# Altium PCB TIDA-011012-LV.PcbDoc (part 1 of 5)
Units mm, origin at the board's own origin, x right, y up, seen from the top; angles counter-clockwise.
Board outline 250 x 280 mm, 4 copper layers (Top Layer, Layer 1, Layer 2, Bottom Layer), stack 2.208 mm thick; 410 components, 230 nets, 1280 pads, 1868 vias.
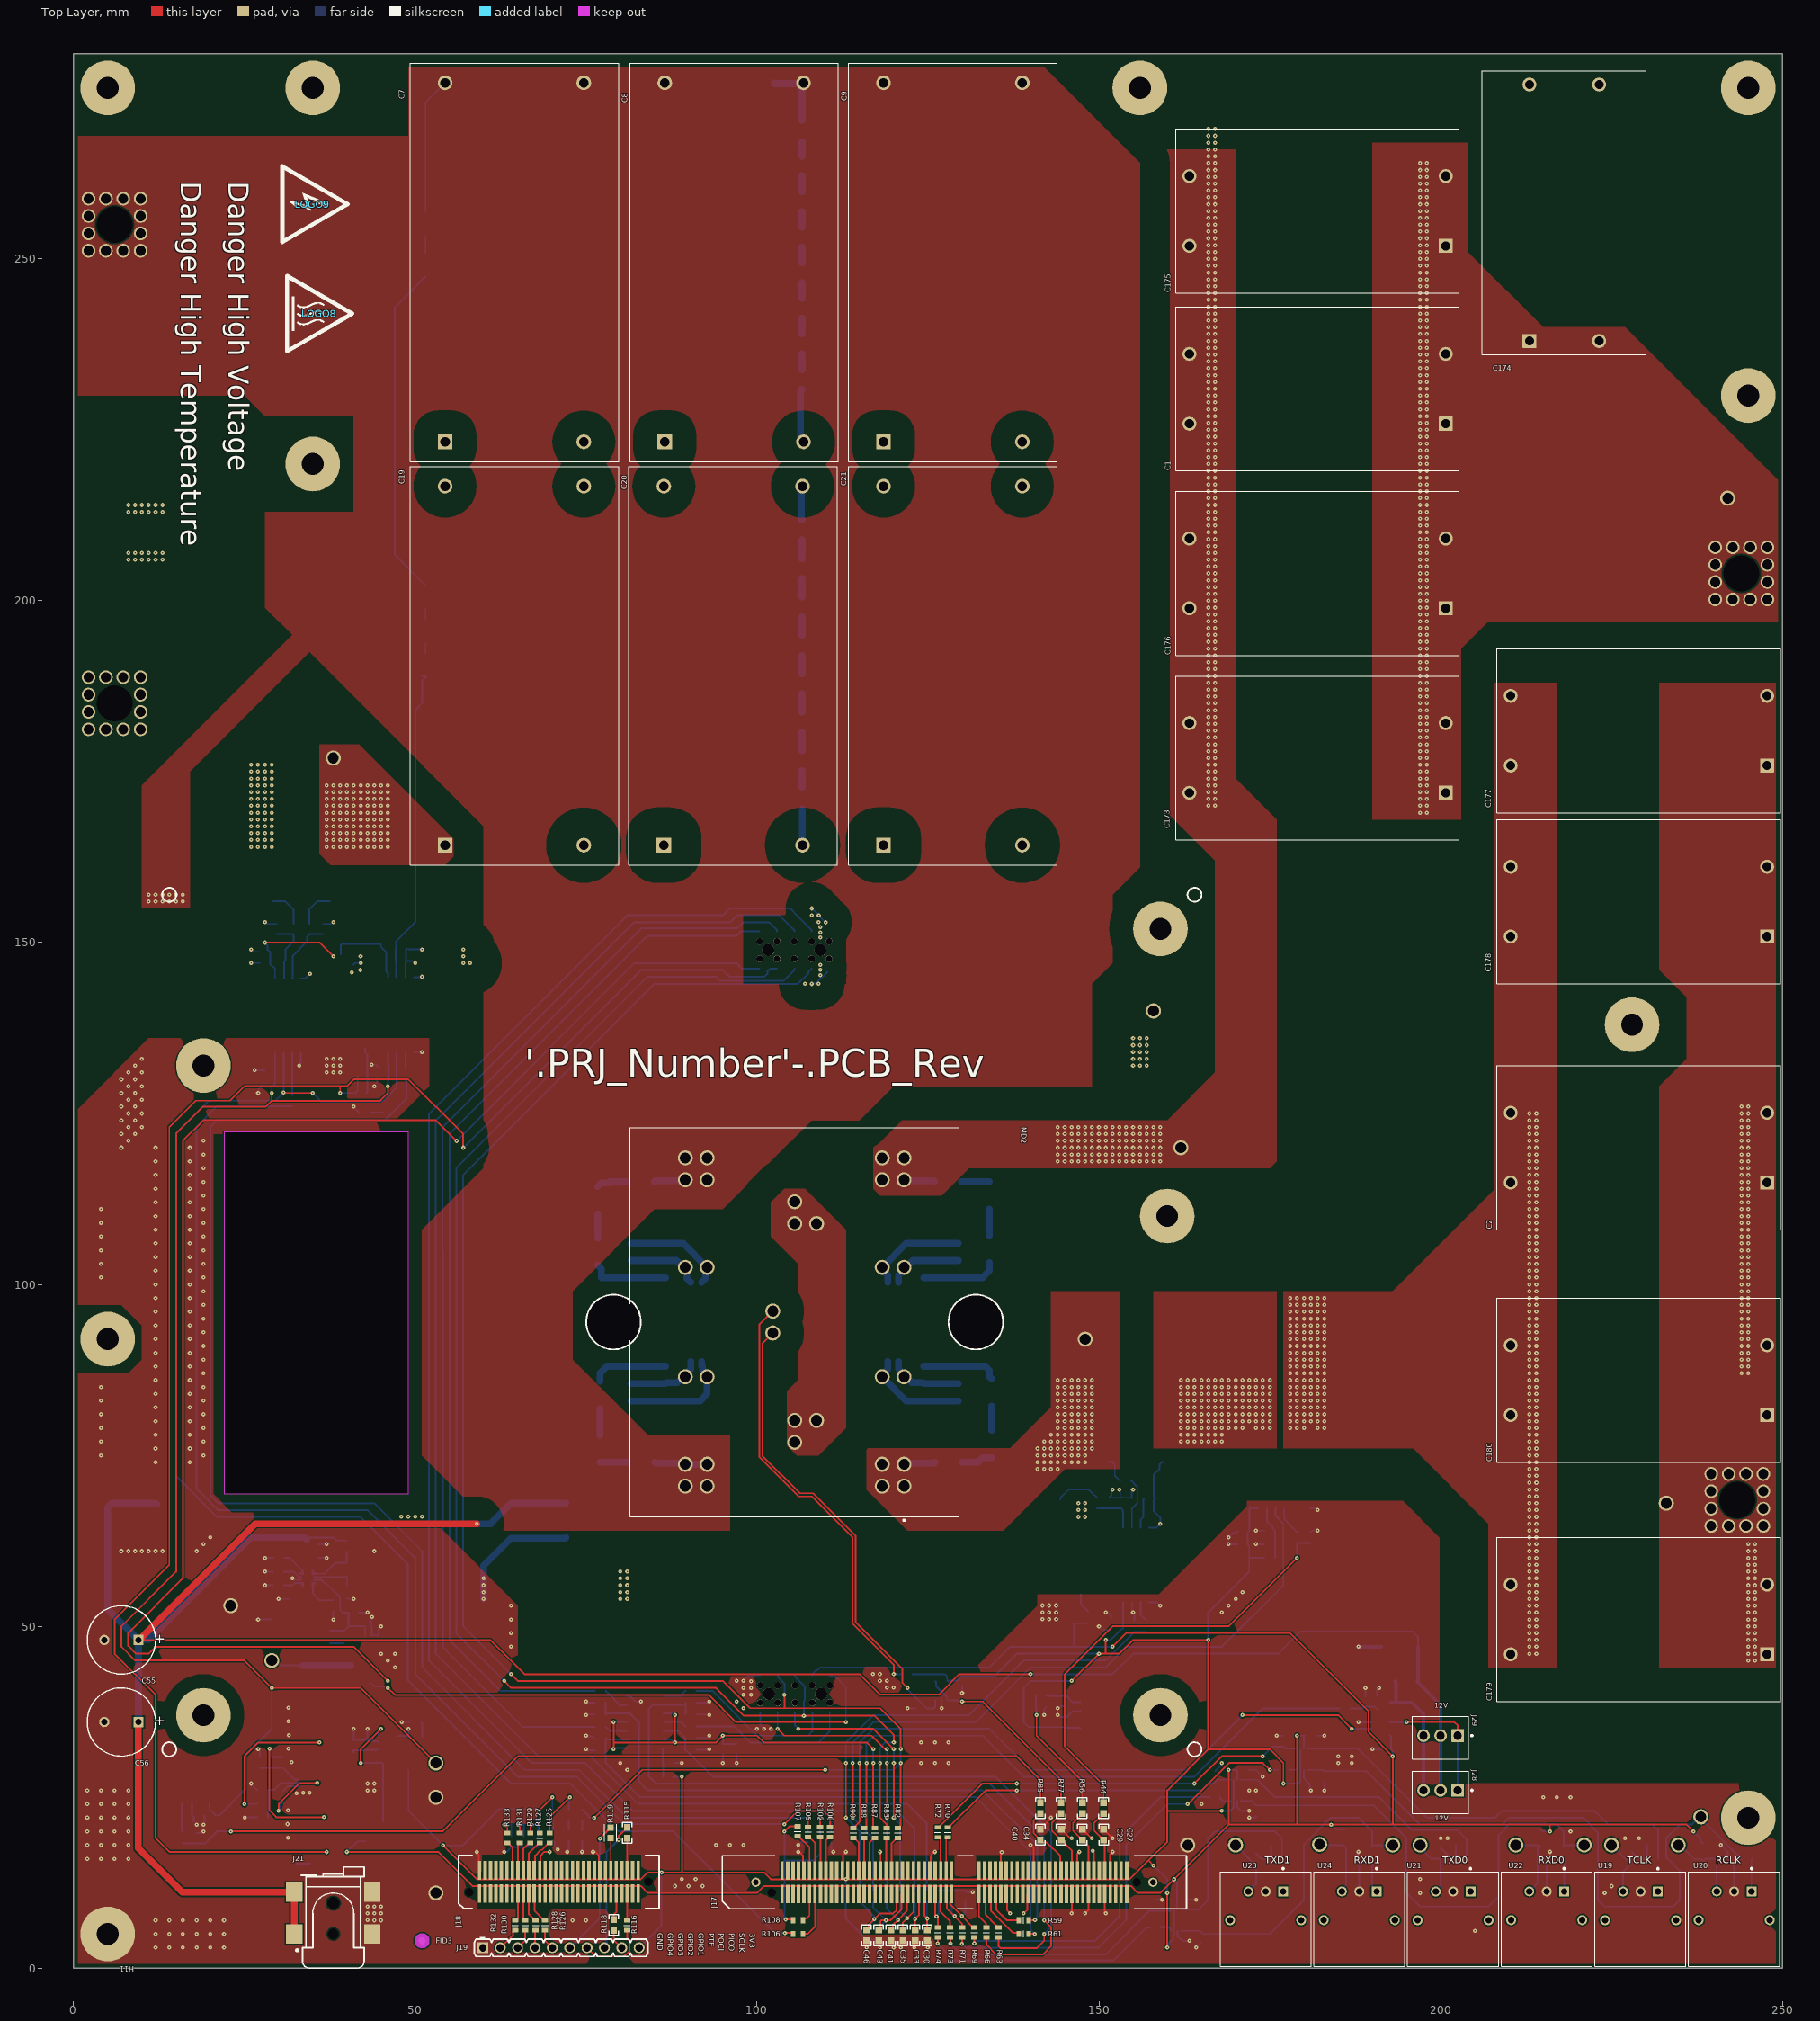
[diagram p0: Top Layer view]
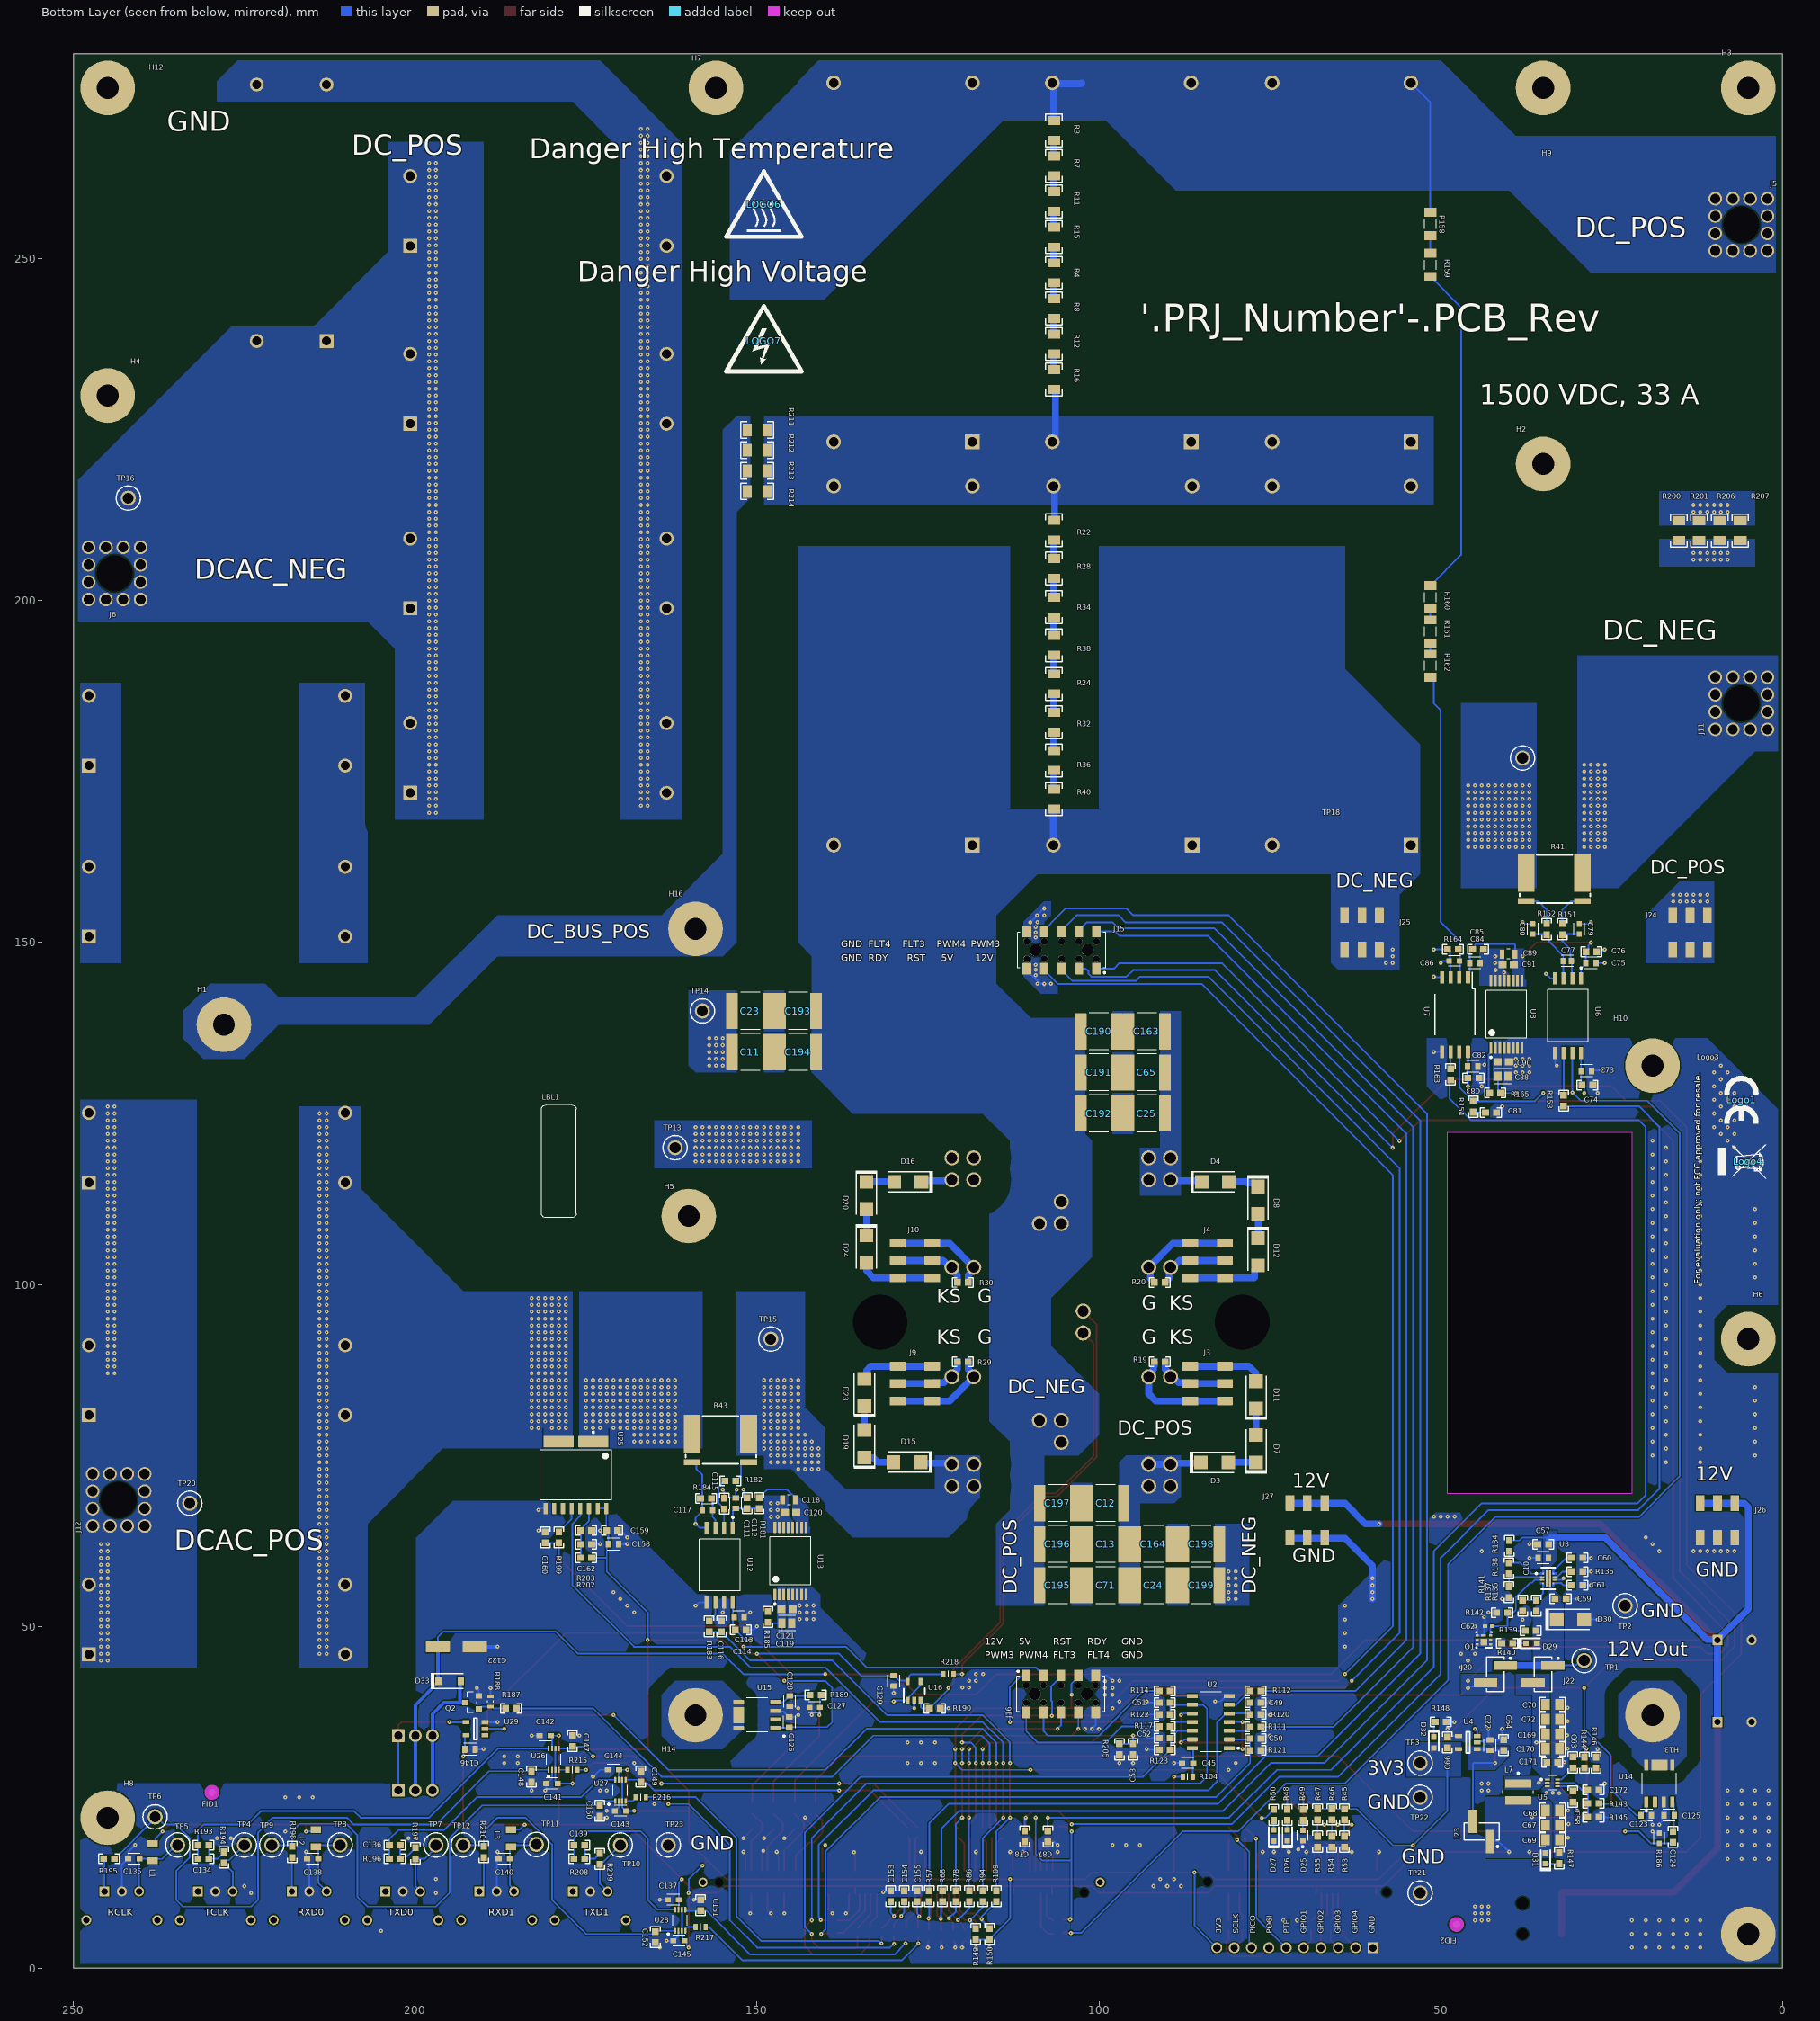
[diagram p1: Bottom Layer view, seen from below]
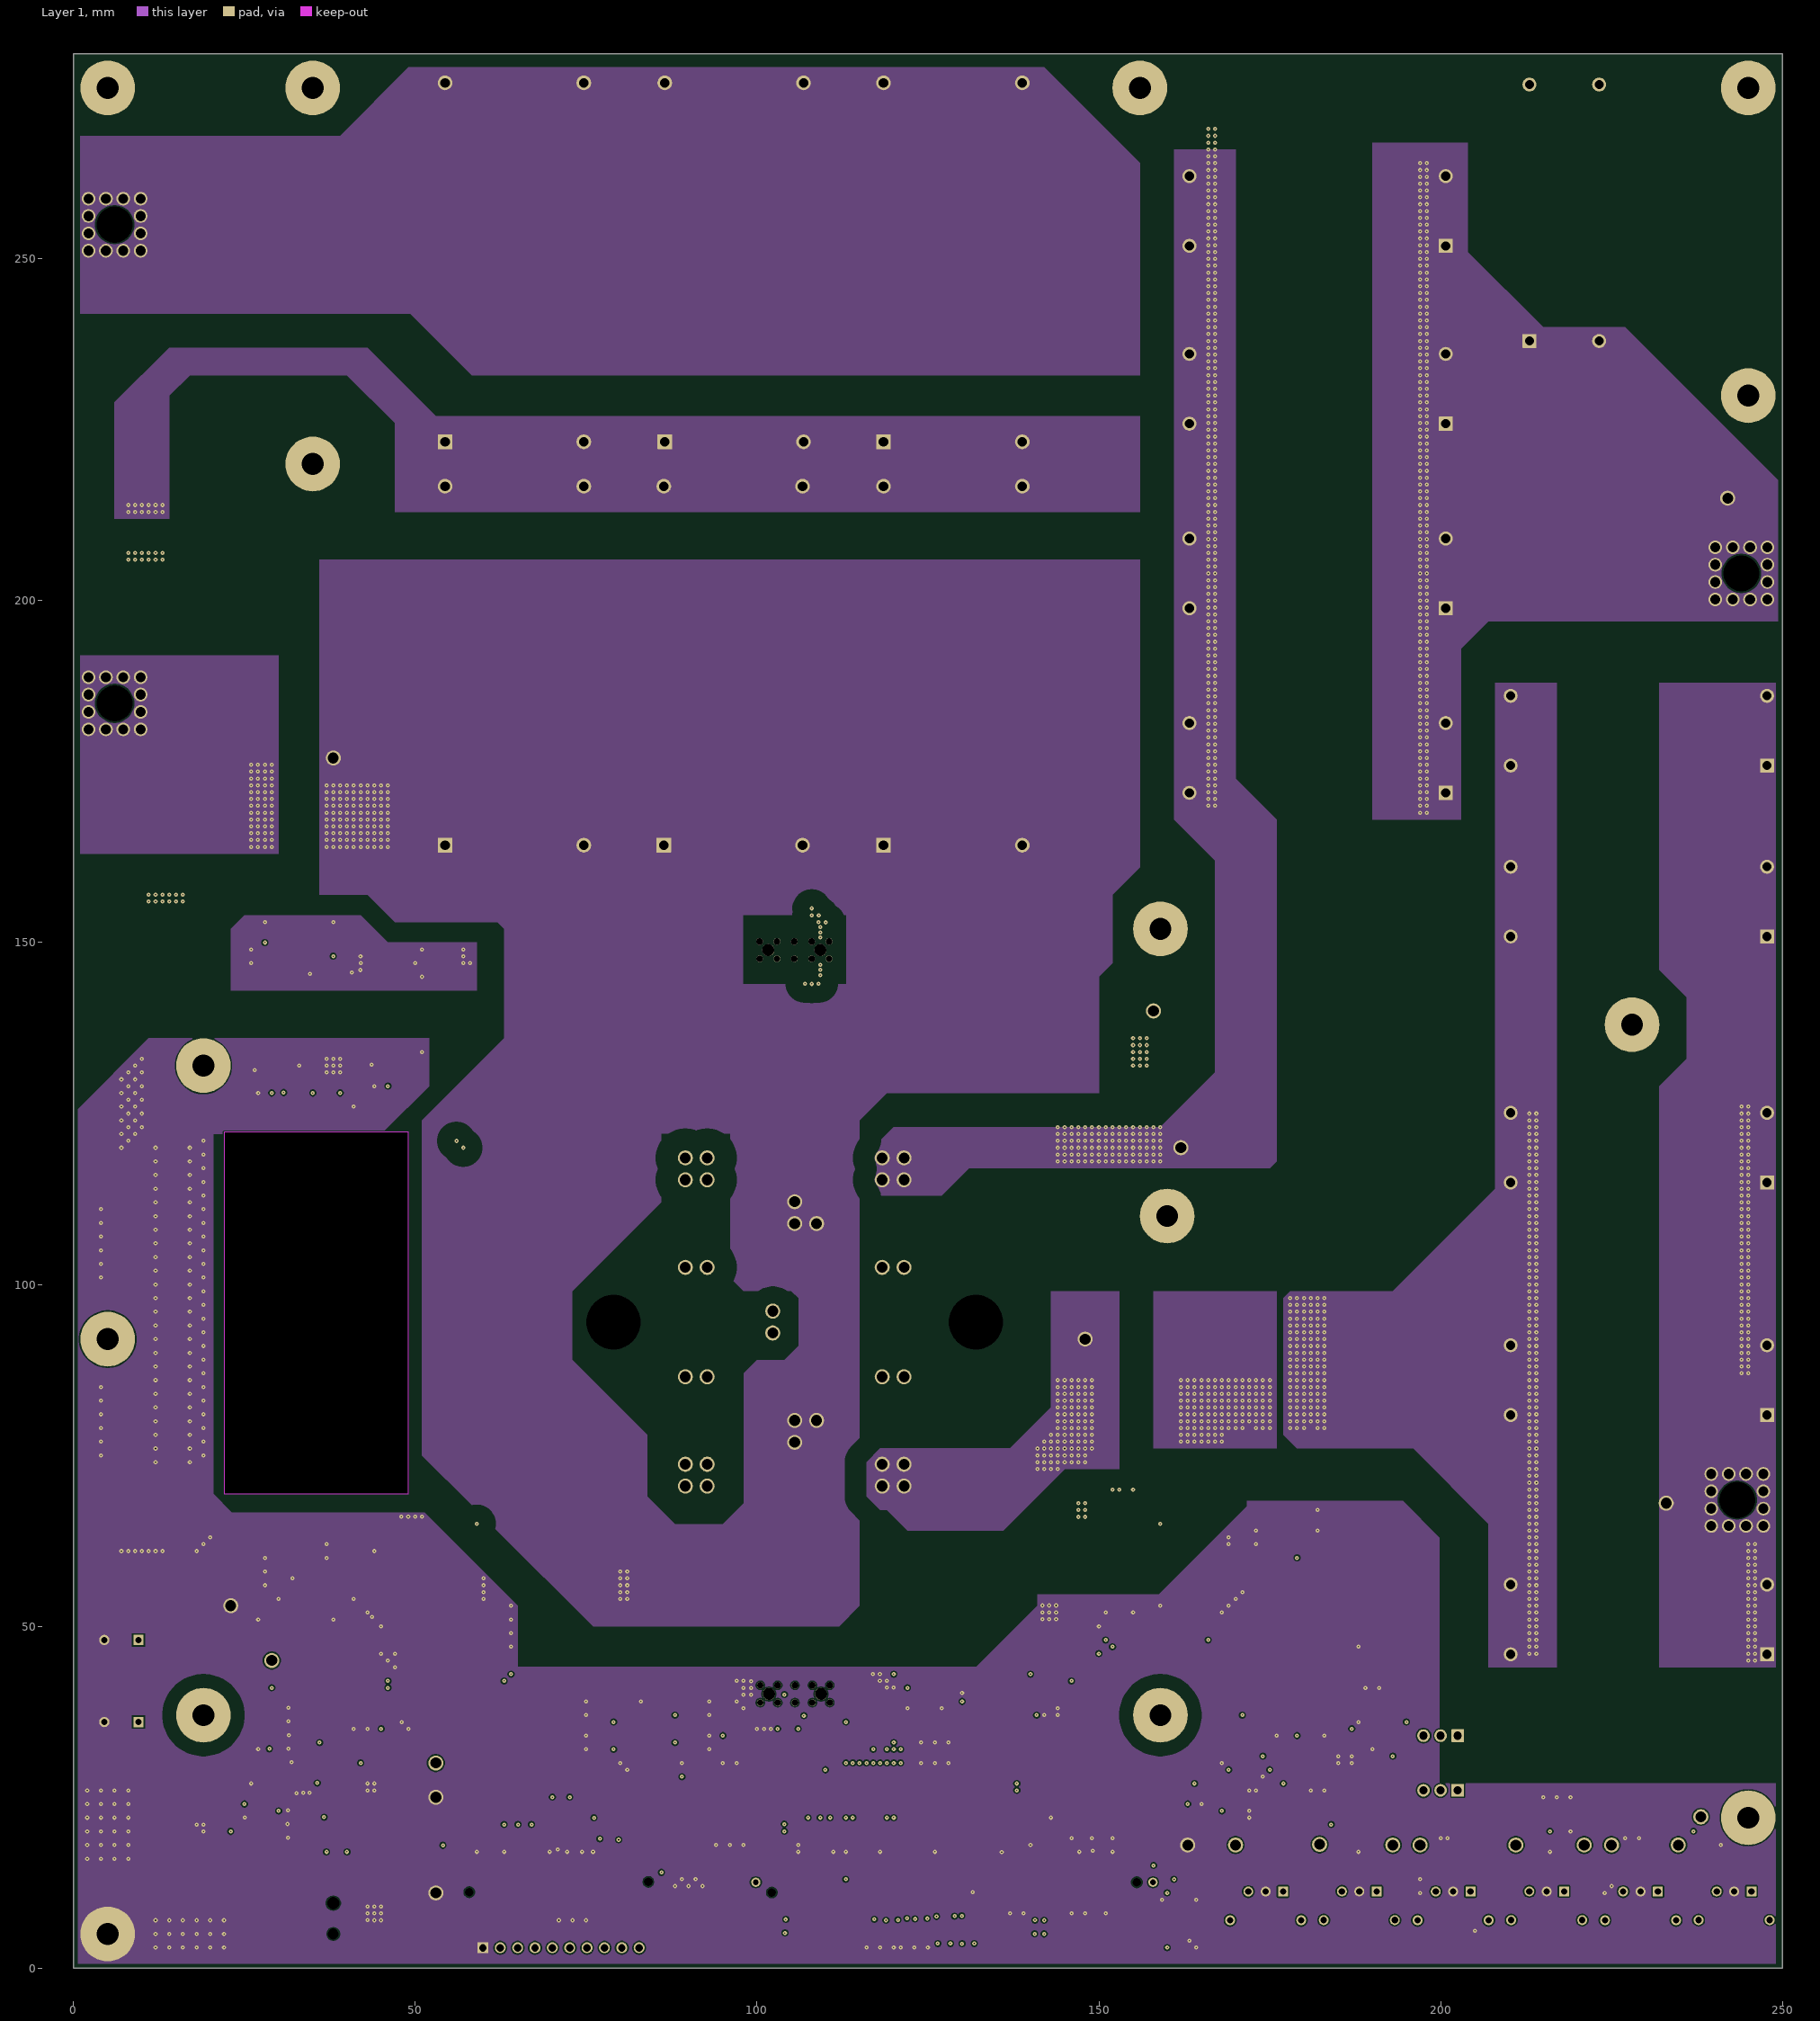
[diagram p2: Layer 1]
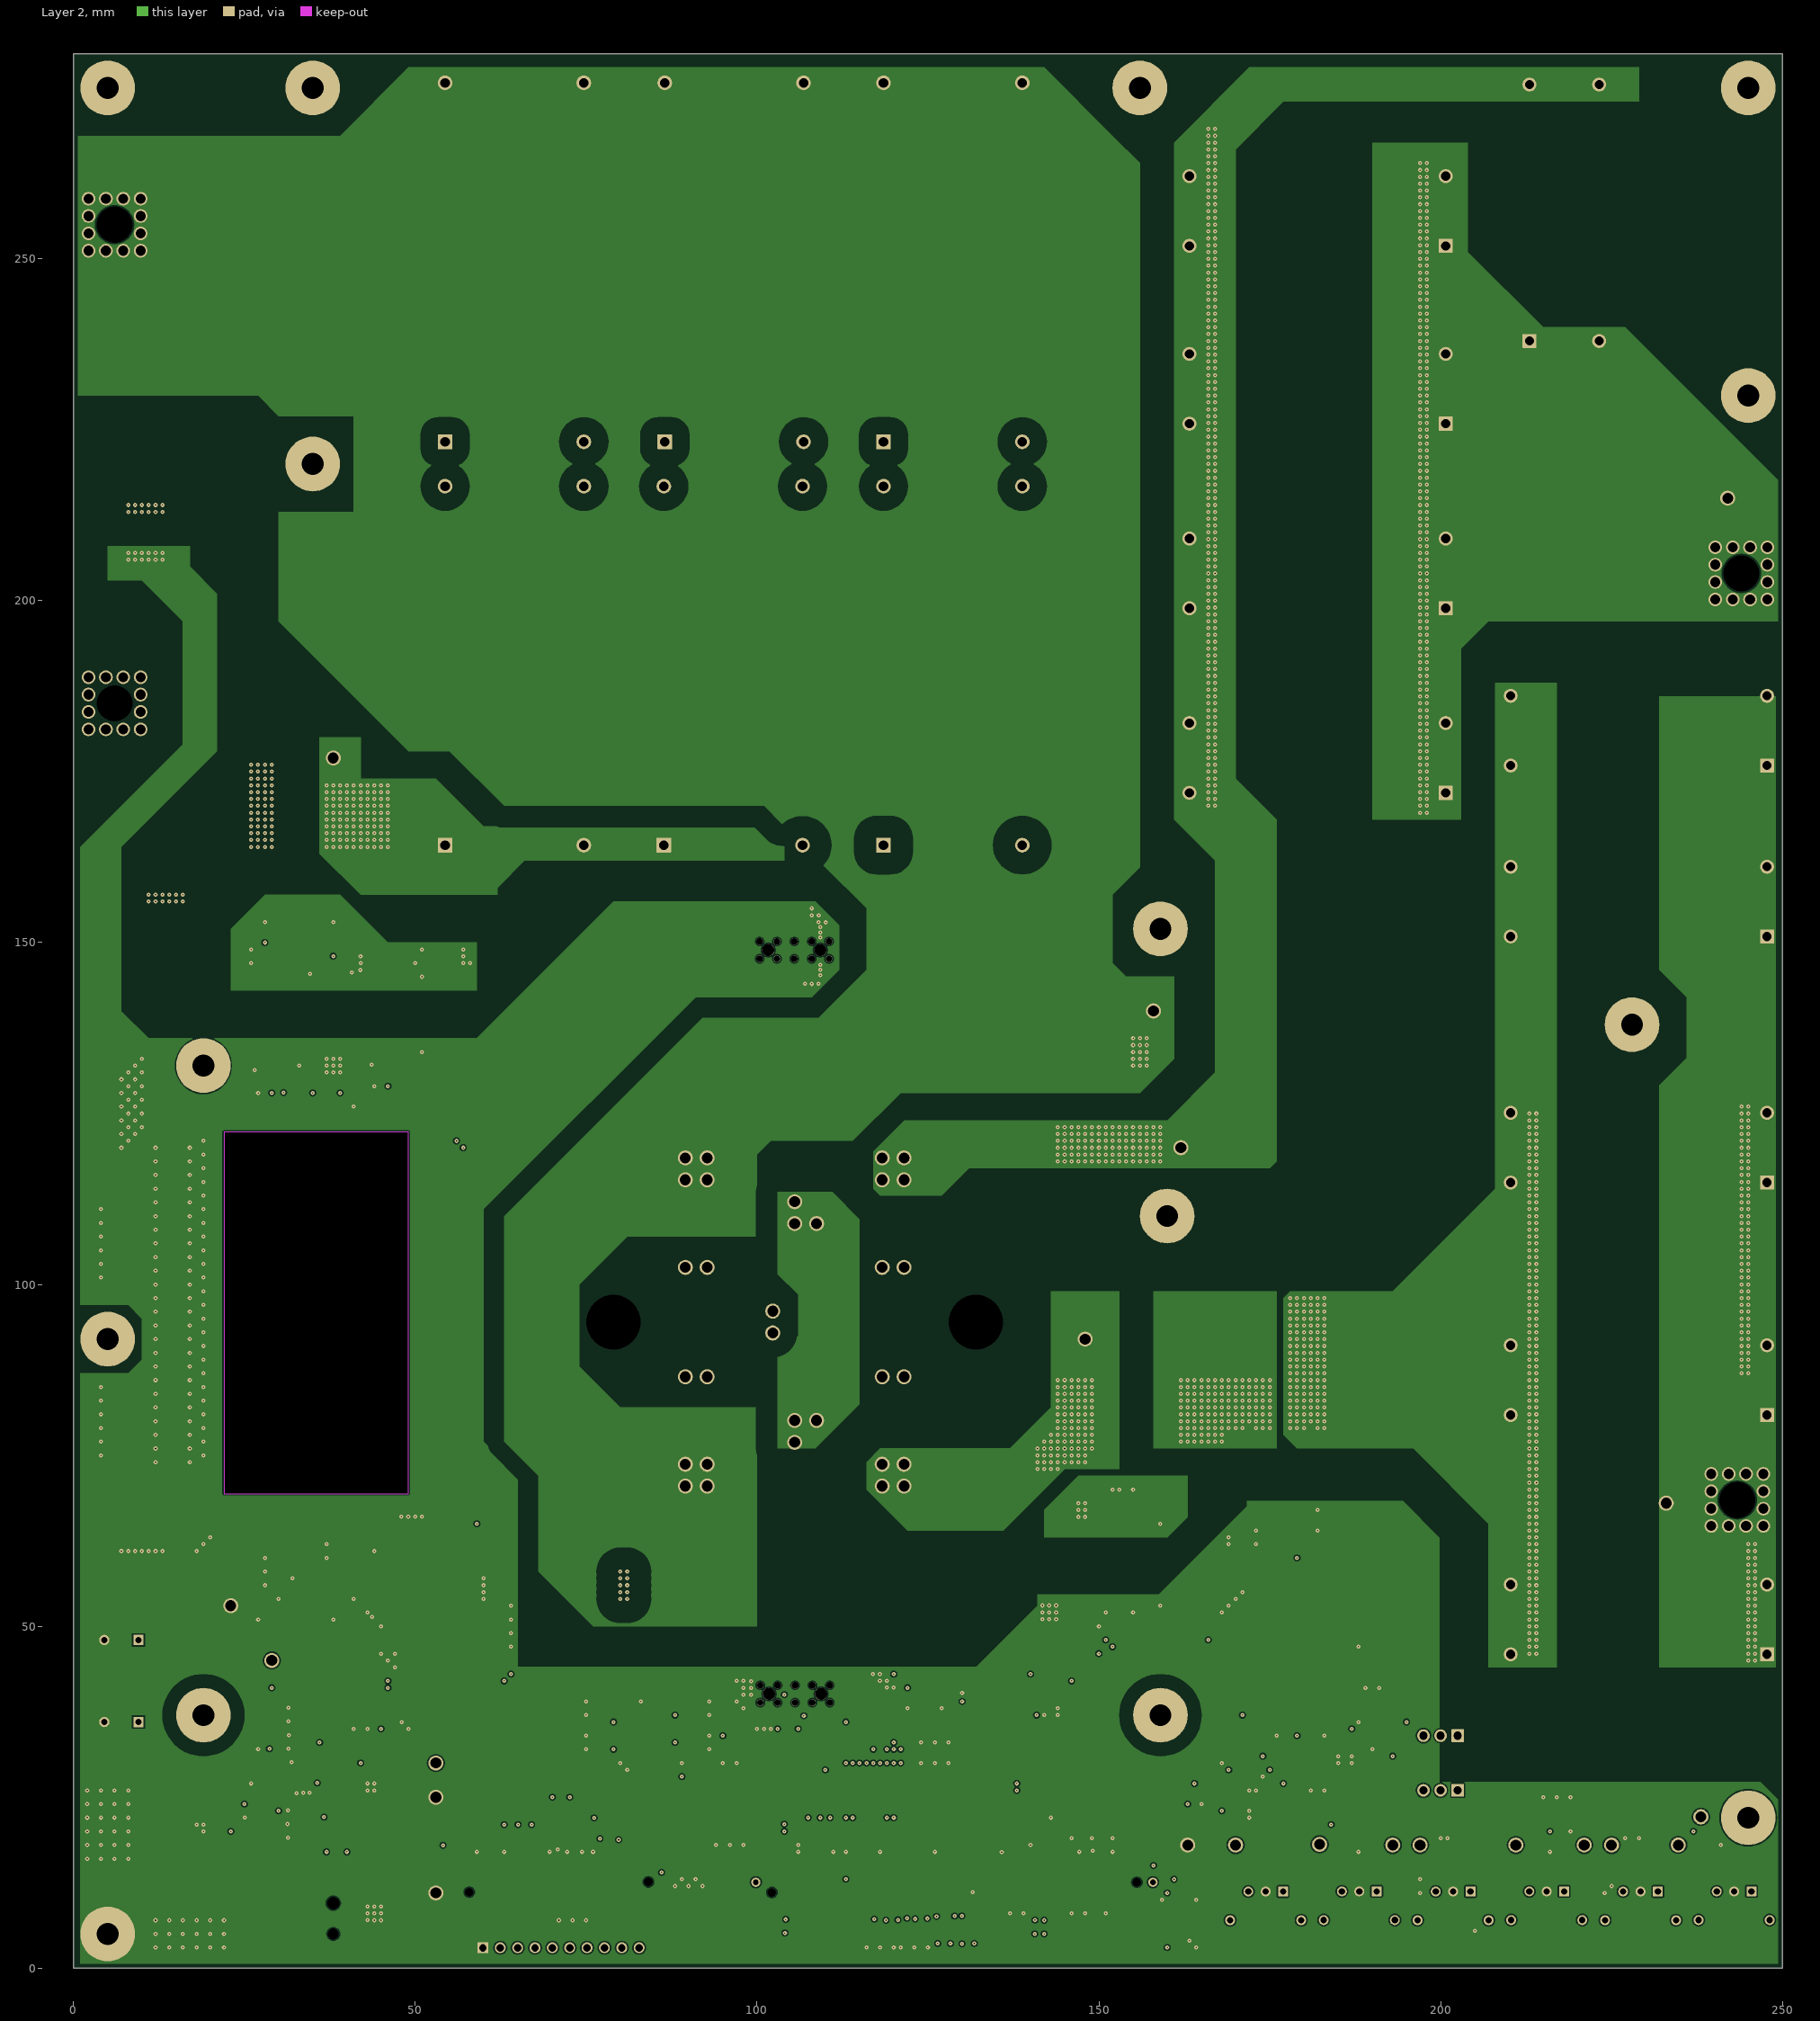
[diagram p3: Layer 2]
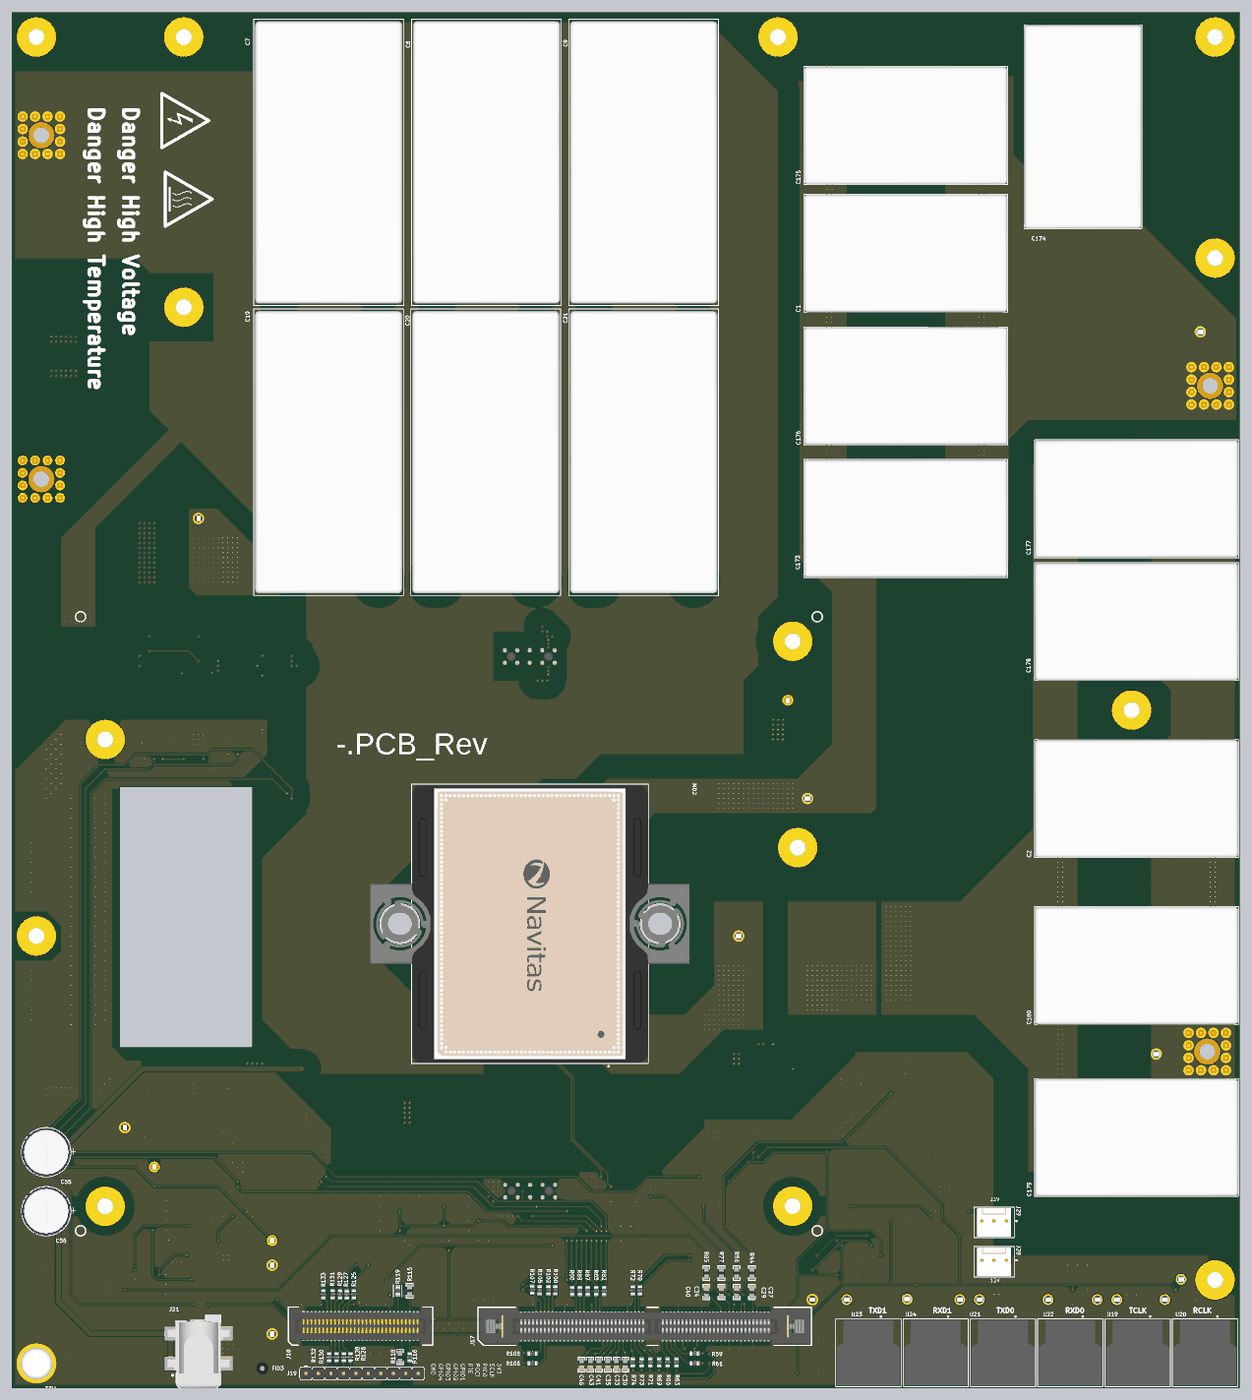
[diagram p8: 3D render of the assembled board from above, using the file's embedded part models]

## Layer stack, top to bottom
Top Solder: solder mask 0.0102, Solder Resist, Dk 3.5
Top Layer: signal copper 0.105
Dielectric 3: prepreg 0.0711, PP-006, Dk 4.1
Dielectric 1: prepreg 0.0711, PP-006, Dk 4.1
Layer 1: signal copper 0.105
Dielectric1: core 1.5037, FR-4 High Tg, Dk 4.8
Layer 2: signal copper 0.105
Dielectric 2: prepreg 0.0711, PP-006, Dk 4.1
Dielectric 4: prepreg 0.0711, PP-006, Dk 4.1
Bottom Layer: signal copper 0.105
Bottom Solder: solder mask 0.0102, Solder Resist, Dk 3.5

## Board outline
0,0 250,0 250,280 0,280
cut-out: 22,69.4 49,69.4 49,122.3 22,122.3

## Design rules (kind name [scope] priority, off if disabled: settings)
AcuteAngle [All] p1: minimum=4.50000000000000E+0001 checktracksonly=FALSE
AssemblyTestPointUsage [All] p1: valid=2
BoardOutlineClearance BoardOutlineClearance_MountingHoles [OnCopper and InComponentClass('Mounting Holes')] p1: gap=1 ignorepadtopadclearanceinfootprint=FALSE
BoardOutlineClearance BoardOutlineClearance_Poly [OnCopper and IsPoly] p2: gap=0.635 ignorepadtopadclearanceinfootprint=FALSE
BoardOutlineClearance [OnCopper and Not InComponentClass('Logo') and not InComponentClass('FiducialMark') and not InRegion(1000,500,4000,800) and not InPoly] p3: gap=1.016 ignorepadtopadclearanceinfootprint=FALSE
Clearance MetalStandofftempSense [InNet('NetH13_1')OR InNet('NetH14_1')] p1: gap=2 ignorepadtopadclearanceinfootprint=TRUE
Clearance Clearance_HV_DC_P_OutLayer_A [InNetClass('HV_DC_P') and (OnLayer('Top Layer') or OnLayer('Bottom Layer') or OnLayer('Multi-Layer')) vs (InNetClass('HV_DC_N') OR InNetClass('HV_AC_N') OR InNetClass('HV_AC_P') OR InNetClass('HV_DC_SN_N') OR InNetClass('HV_DC_SN_P') )  and (OnLayer('Top Layer') or OnLayer('Bottom Layer') or OnLayer('Multi-Layer'))] p2: gap=4.4 ignorepadtopadclearanceinfootprint=TRUE
Clearance Clearance_HVM_OutLayer_A [InNetClass('HVM') and (OnLayer('Top Layer') or OnLayer('Bottom Layer') or OnLayer('Multi-Layer')) vs (InNetClass('HV_DC_N') OR InNetClass('HV_AC_N') OR InNetClass('HV_AC_P') OR InNetClass('HV_DC_SN_N') OR InNetClass('HV_DC_SN_P') OR InNetClass('HV_DC_P') )  and (OnLayer('Top Layer') or OnLayer('Bottom Layer') or OnLayer('Multi-Layer'))] p3: gap=3.5 ignorepadtopadclearanceinfootprint=TRUE
Clearance Clearance_HV_DC_N_OutLayer_A [InNetClass('HV_DC_N') and (OnLayer('Top Layer') or OnLayer('Bottom Layer') or OnLayer('Multi-Layer')) vs (InNetClass('HV_DC_P') OR InNetClass('HV_AC_N') OR InNetClass('HV_AC_P') OR InNetClass('HV_DC_SN_N') OR InNetClass('HV_DC_SN_P'))   and (OnLayer('Top Layer') or OnLayer('Bottom Layer') or OnLayer('Multi-Layer'))] p4: gap=4.4 ignorepadtopadclearanceinfootprint=TRUE
Clearance Clearance_HV_AC_N_OutLayer_A [InNetClass('HV_AC_N') and  (OnLayer('Top Layer') or OnLayer('Bottom Layer') or OnLayer('Multi-Layer')) vs (InNetClass('HV_DC_N') OR InNetClass('HV_DC_P') OR InNetClass('HV_AC_P') OR InNetClass('HV_DC_SN_N') OR InNetClass('HV_DC_SN_P')  )   and (OnLayer('Top Layer') or OnLayer('Bottom Layer') or OnLayer('Multi-Layer'))] p5: gap=4.4 ignorepadtopadclearanceinfootprint=TRUE
Clearance Clearance_HV_DC_SN_N_OutLayer_A [InNetClass('HV_DC_SN_N')  and (OnLayer('Top Layer') or OnLayer('Bottom Layer') or OnLayer('Multi-Layer')) vs (InNetClass('HV_DC_N') OR InNetClass('HV_DC_P') OR InNetClass('HV_AC_P') OR InNetClass('HV_AC_N') OR InNetClass('HV_DC_SN_P'))  and (OnLayer('Top Layer') or OnLayer('Bottom Layer') or OnLayer('Multi-Layer'))] p6: gap=4.4 ignorepadtopadclearanceinfootprint=TRUE
Clearance Clearance_HV_DC_SN_P_OutLayer_A [InNetClass('HV_DC_SN_P')  and (OnLayer('Top Layer') or OnLayer('Bottom Layer') or OnLayer('Multi-Layer')) vs (InNetClass('HV_DC_N') OR InNetClass('HV_DC_P') OR InNetClass('HV_AC_P') OR InNetClass('HV_DC_SN_N') OR InNetClass('HV_AC_N')) and  (OnLayer('Top Layer') or OnLayer('Bottom Layer') or OnLayer('Multi-Layer'))] p7: gap=4.4 ignorepadtopadclearanceinfootprint=TRUE
Clearance Clearance_HV_AC_P_OutLayer_A [InNetClass('HV_AC_P')       and (OnLayer('Top Layer') or OnLayer('Bottom Layer') or OnLayer('Multi-Layer')) vs (InNetClass('HV_DC_N') OR InNetClass('HV_DC_P') OR InNetClass('HV_AC_N') OR InNetClass('HV_DC_SN_N') OR InNetClass('HV_DC_SN_P'))   and (OnLayer('Top Layer') or OnLayer('Bottom Layer') or OnLayer('Multi-Layer'))] p8: gap=3.2 ignorepadtopadclearanceinfootprint=TRUE
Clearance Clearance_HV_DC_P_InnerLayers [InNetClass('HV_DC_P') vs InNetClass('HV_DC_N') OR InNetClass('HV_AC_N') OR InNetClass('HV_AC_P') OR InNetClass('HV_DC_SN_N') OR InNetClass('HV_DC_SN_P')] p9: gap=3.2 ignorepadtopadclearanceinfootprint=TRUE
Clearance Clearance_HVM_InnerLayers [InNetClass('HVM') vs (InNetClass('HV_DC_N') OR InNetClass('HV_AC_N') OR InNetClass('HV_AC_P') OR InNetClass('HV_DC_SN_N') OR InNetClass('HV_DC_SN_P') OR InNetClass('HV_DC_P') )] p10: gap=2.5 ignorepadtopadclearanceinfootprint=TRUE
Clearance Clearance_HV_DC_N_InnerLayers [InNetClass('HV_DC_N') vs InNetClass('HV_DC_P') OR InNetClass('HV_AC_N') OR InNetClass('HV_AC_P') OR InNetClass('HV_DC_SN_N') OR InNetClass('HV_DC_SN_P')] p11: gap=3.2 ignorepadtopadclearanceinfootprint=TRUE
Clearance Clearance_HV_AC_N_InnerLayers [InNetClass('HV_AC_N') vs InNetClass('HV_DC_N') OR InNetClass('HV_DC_P') OR InNetClass('HV_AC_P') OR InNetClass('HV_DC_SN_N') OR InNetClass('HV_DC_SN_P')] p12: gap=3.2 ignorepadtopadclearanceinfootprint=TRUE
Clearance Clearance_HV_AC_P_InnerLayers [InNetClass('HV_AC_P') vs InNetClass('HV_DC_N') OR InNetClass('HV_DC_P') OR InNetClass('HV_AC_N') OR InNetClass('HV_DC_SN_N') OR InNetClass('HV_DC_SN_P')] p13: gap=3.2 ignorepadtopadclearanceinfootprint=TRUE
Clearance Clearance_HV_DC_SN_N_InnerLayers [InNetClass('HV_DC_SN_N') vs InNetClass('HV_DC_N') OR InNetClass('HV_DC_P') OR InNetClass('HV_AC_P') OR InNetClass('HV_AC_N') OR InNetClass('HV_DC_SN_P')] p14: gap=3.2 ignorepadtopadclearanceinfootprint=TRUE
Clearance Clearance_HV_DC_SN_P_InnerLayers [InNetClass('HV_DC_SN_P') vs InNetClass('HV_DC_N') OR InNetClass('HV_DC_P') OR InNetClass('HV_AC_P') OR InNetClass('HV_DC_SN_N') OR InNetClass('HV_AC_N')] p15: gap=3.2 ignorepadtopadclearanceinfootprint=TRUE
Clearance Clearance_Keepouts [((IsTrack Or IsArc) And Not InPoly) And IsFree and IsKeepOut vs ((IsTrack Or IsArc) And Not InPoly) And IsFree and IsKeepOut] p16: gap=0 ignorepadtopadclearanceinfootprint=FALSE
Clearance Clearance_Poly [InPolygon] p17: gap=0.2 ignorepadtopadclearanceinfootprint=TRUE
Clearance Clearance_FiducialMark [IsKeepOut and InComponentClass('FiducialMark') vs IsPad and InComponentClass('FiducialMark')] p18: gap=0 ignorepadtopadclearanceinfootprint=FALSE
Clearance [All] p19: gap=0.2 ignorepadtopadclearanceinfootprint=TRUE
ComponentClearance ComponentClearance_MountingHoles_FiducialMarks [InComponentClass('Mounting Holes') vs InComponentClass('FiducialMark')] p1: gap=1.27 collisioncheckmode=3 verticalgap=0.254 showdistances=FALSE
ComponentClearance ComponentClearance_Shunt [InComponentClass('Header') vs InComponentClass('Shunt')] p2: gap=0 collisioncheckmode=3 verticalgap=0 showdistances=FALSE
ComponentClearance ComponentClearance_Logo [InComponentClass('Logo')] p3: gap=0.762 collisioncheckmode=3 verticalgap=0.254 showdistances=FALSE
ComponentClearance ComponentClearance_ScrewToNut [(HasFootprint('NY PMS 440 0025 PH')) vs (HasFootprint('Keystone_1902C'))] p4: gap=0.127 collisioncheckmode=3 verticalgap=0.254 showdistances=FALSE
ComponentClearance ComponentClearance_MountingHoles [InComponentClass('Mounting Holes')] p5: gap=2 collisioncheckmode=3 verticalgap=2540 showdistances=FALSE
ComponentClearance ComponentClearance_SmallPassives [HasFootprint('0201*') or HasFootprint('0402*') or HasFootprint('0508') or HasFootprint('0603*') or HasFootprint('0612') or HasFootprint('0805*') or HasFootprint('0815*') or HasFootprint('0830*') or HasFootprint('1206*') or HasFootprint('1210*') or HasFootprint('1808*') or HasFootprint('1812*') or HasFootprint('1825*') or HasFootprint('2010*') or HasFootprint('2220*') or HasFootprint('2225*') or HasFootprint('2512*') or HasFootprint('2728*') or HasFootprint('3518*') vs HasFootprint('0201*') or HasFootprint('0402*') or HasFootprint('0508') or HasFootprint('0603*') or HasFootprint('0612') or HasFootprint('0805*') or HasFootprint('0815*') or HasFootprint('0830*') or HasFootprint('1206*') or HasFootprint('1210*') or HasFootprint('1808*') or HasFootprint('1812*') or HasFootprint('1825*') or HasFootprint('2010*') or HasFootprint('2220*') or HasFootprint('2225*') or HasFootprint('2512*') or HasFootprint('2728*') or HasFootprint('3518*')] p6: gap=0.38 collisioncheckmode=3 verticalgap=0.254 showdistances=FALSE
ComponentClearance ComponentClearance_THtoSMT [IsThruComponent vs IsSMTComponent] p7: gap=0.762 collisioncheckmode=3 verticalgap=0.762 showdistances=FALSE
ComponentClearance ComponentClearance_THtoTH [IsThruComponent vs IsThruComponent] p8: gap=0.508 collisioncheckmode=3 verticalgap=0.762 showdistances=FALSE
ComponentClearance [All] p9: gap=0.508 collisioncheckmode=3 verticalgap=0.254 showdistances=FALSE
DiffPairsRouting [All] p1: maxlimit=2.54 minlimit=0.254 mostfreqgap=0.254 toplayer_minwidth=0.381 toplayer_maxwidth=0.381 toplayer_prefwidth=0.381 midlayer1_minwidth=0.381 midlayer1_maxwidth=0.381 midlayer1_prefwidth=0.381 midlayer2_minwidth=0.381 midlayer2_maxwidth=0.381 midlayer2_prefwidth=0.381 bottomlayer_minwidth=0.381 bottomlayer_maxwidth=0.381 bottomlayer_prefwidth=0.381 maxuncoupledlength=25.4
FabricationTestPointUsage TestPointUsage [All] p1: valid=2 allowmultiple=FALSE
FabricationTestpoint Testpoint [All] p1: side=3 testpointundercomponent=TRUE minsize=1.016 maxsize=2.54 preferedsize=1.524 minholesize=0 maxholesize=1.016 preferedholesize=0.813 testpointgrid=0.025 allowsidetop=TRUE allowsidebottom=TRUE usegrid=TRUE gridtolerance=0
FanoutControl Fanout_LCC [IsLCC] p1: bgadir=Out bgaviamode=Centered fanoutstyle=Auto fanoutdirection=Alternating viagrid=0.025 // Fanout_LCC (Default Rule)
FanoutControl Fanout_BGA [IsBGA] p2: bgadir=Out bgaviamode=Centered fanoutstyle=Auto fanoutdirection=Alternating viagrid=0.025 // Fanout_BGA (Default Rule)
FanoutControl Fanout_Default [All] p4: bgadir=Out bgaviamode=Centered fanoutstyle=Auto fanoutdirection=Alternating viagrid=0.025 // Fanout_Default (Default Rule)
FanoutControl Fanout_Small [(CompPinCount < 5)] p5: bgadir=Out bgaviamode=Centered fanoutstyle=Auto fanoutdirection=OutThenIn viagrid=0.025 // Fanout_Small (Default Rule)
HoleSize [All] p1: absolutevalues=TRUE maxlimit=6.375 minlimit=0.2 maxpercent=80.000 minpercent=20.000
MinimumAnnularRing MinimumAnnularRing_ThermalPadVias [IsVia and InAnyComponent] p1: minimumring=0.15
MinimumAnnularRing [All] p2: minimumring=0.2
MinimumSolderMaskSliver MinimumSolderMaskSliver_Logo [InComponentClass('Logo') vs InComponentClass('Logo')] p1: minsoldermaskwidth=0.018
MinimumSolderMaskSliver [All] p2: minsoldermaskwidth=0.1
PlaneConnect [All] p1: planeconnectstyle=Relief reliefexpansion=0.254 reliefentries=4 reliefconductorwidth=0.254 reliefairgap=0.254
PolygonConnect [All] p1: connectstyle=Direct reliefconductorwidth=0.254 reliefentries=4 polygonreliefangle="90 Angle" airgapwidth=0.254
RoutingLayers [All] p1: top layer_v5=TRUE mid layer 1_v5=FALSE mid layer 2_v5=FALSE bottom layer_v5=TRUE
RoutingVias ThermalPadVias [IsVia and InAnyComponent] p1: holewidth=0.2 width=0.6 viastyle="Through Hole" minholewidth=0.2 minwidth=0.5 maxholewidth=0.33 maxwidth=0.6
RoutingVias [All] p2: holewidth=0.2 width=0.6 viastyle="Through Hole" minholewidth=0.2 minwidth=0.6 maxholewidth=1.016 maxwidth=10 useviatemplates=TRUE viatemplateguid#1={B147BCFB-7244-4C41-95E0-E515B48E21B2} viatemplatename#1=v60h20m0mx0
SilkToBoardRegionClearance [Not ((IsComment or IsDesignator) And (Hide <> 'False')) and not InRegion(1000,500,4000,800)] p1:
SilkToSilkClearance SilkToSilkClearance_Pb-FreeLogo [(HasFootprint('Pb-Free_Overlay_Medium') OR HasFootprint('Pb-Free_Overlay_Small')) vs (HasFootprint('Pb-Free_Overlay_Medium') OR HasFootprint('Pb-Free_Overlay_Small'))] p1: silktosilkclearance=0
SilkToSilkClearance [All] p2: silktosilkclearance=0
SilkToSolderMaskClearance SilkToComponentPadClearance [(IsPad or IsFill or IsRegion) and InAnycomponent] p1: minsilkscreentomaskgap=0.1 clearancetoexposedcopper=TRUE
SilkToSolderMaskClearance "Silk to Solder Mask Opening" [All] p2: minsilkscreentomaskgap=0.1 clearancetoexposedcopper=FALSE
SolderMaskExpansion [All] p1: expansion=0.05 istentingtop=FALSE
UnRoutedNet [All] p1: checkbadconnections=TRUE
Width [All] p1: maxlimit=5 minlimit=0.25 preferedwidth=0.25 checkconnectedcopper=TRUE
13 further rules are at their usual default settings.

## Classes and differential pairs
net class HV_DC_SN_P: DC_DS3 DC_G3 DC_KS3 NetC1_1 NetC1_2
net class HV_DC_P: DC_POS
net class HVM: 3V3 5V 12V 12V_FET_DRAIN 12V_IN 12V_OUT CLK_MOD_DC DATA_I_DC DATA_V_DC DC_BUF_PMW1 DC_BUF_PMW2 DC_BUF_PMW3 DC_BUF_PMW4 DC_FAULT_FET1 DC_FAULT_FET2 DC_FAULT_FET3 DC_FAULT_FET4 DC_GD_RDY DC_GD_RST/EN DC_OC DC_OC_CMP DC_PWM1 DC_PWM2 DC_PWM3 DC_PWM4 DEBUG_GPIO1 DEBUG_GPIO2 DEBUG_GPIO3 DEBUG_GPIO4 EF_dVdt EF_EN EF_ILIM EF_ITIMER EF_OVLO EF_PG EF_PGTH FAN_EN FAN_PWM FSIRXA_CLK FSIRXA_D0 FSITXA_CLK FSITXA_D0 GND I_HALL ID1 ID2 ID3 LED_GREEN LED_RED NetC7_1 NetC22_1 NetC27_1 NetC29_1 NetC30_1 NetC33_1 NetC34_1 NetC35_1 NetC40_1 NetC41_1 NetC43_1 NetC45_2 NetC46_1 NetC58_1 NetC58_2 NetC63_2 NetC70_1 NetC81_1 NetC125_1 NetC128_1 NetC134_1 NetC135_2 NetC136_1 NetC138_2 NetC139_1 NetC140_2 NetC153_1 NetC154_1 NetC155_1 NetC162_1 NetC172_1 NetD25_2 NetD26_2 NetD27_2 NetD29_1 NetD31_1 NetD32_1 NetD33_2 NetH1_1 NetH13_1 NetH14_1 NetJ17_3 NetJ17_4 NetJ17_5 NetJ17_6 NetJ17_8 NetJ17_12 NetJ17_14 NetJ17_18 NetJ17_20 NetJ17_23 NetJ17_24 NetJ17_26 NetJ17_27 NetJ17_28 NetJ17_29 NetJ17_30 NetJ17_31 NetJ17_32 NetJ17_33 NetJ17_34 NetJ17_36 NetJ17_37 NetJ17_39 NetJ17_40 NetJ17_41 NetJ17_42 NetJ17_43 NetJ17_44 NetJ17_45 NetJ17_50 NetJ17_52 NetJ17_54 NetJ17_56 NetJ17_57 NetJ17_59 NetJ17_61 NetJ17_62 NetJ17_63 NetJ17_66 NetJ17_79 NetJ17_80 NetJ17_81 NetJ17_82 NetJ17_85 NetJ17_86 NetJ17_87 NetJ17_88 NetJ17_89 NetJ17_90 NetJ17_91 NetJ17_92 NetJ17_93 NetJ17_94 NetJ17_95 NetJ17_96 NetJ17_103 NetJ17_105 NetJ17_107 NetJ17_108 NetJ17_109 NetJ17_110 NetJ17_113 NetJ17_114 NetJ17_115 NetJ17_116 NetJ17_117 NetJ17_118 NetJ17_119 NetJ17_120 NetJ18_121 NetJ18_122 NetJ18_123 NetJ18_124 NetJ18_125 NetJ18_126 NetJ18_127 NetJ18_128 NetJ18_129 NetJ18_130 NetJ18_131 NetJ18_132 NetJ18_133 NetJ18_134 NetJ18_136 NetJ18_137 NetJ18_138 NetJ18_139 NetJ18_140 NetJ18_141 NetJ18_142 NetJ18_143 NetJ18_144 NetJ18_145 NetJ18_146 NetJ18_147 NetJ18_148 NetJ18_149 NetJ18_150 NetJ18_151 NetJ18_152 NetJ18_153 NetJ18_154 NetJ18_155 NetJ18_156 NetJ18_159 NetJ18_160 NetJ18_161 NetJ18_162 NetJ18_163 NetJ18_164 NetJ18_165 NetJ18_166 NetJ18_167 NetJ18_168 NetJ18_169 NetJ18_170 NetJ18_171 NetJ18_172 NetJ18_173 NetJ18_174 NetJ18_175 NetJ18_176 NetJ18_177 NetJ18_178 NetJ28_1 NetQ2_1 NetR111_1 NetR112_1 NetR114_1 NetR117_1 NetR153_1 NetR163_1 NetR165_1 NetR183_1 NetR185_1 NetR194_2 NetR195_1 NetR197_2 NetR198_1 NetR199_1 NetR209_2 NetR210_1 NetR215_2 NetR216_2 NetR217_2 NetU19_4 NetU19_5 NetU20_4 NetU20_5 NetU21_4 NetU21_5 NetU22_4 NetU22_5 NetU23_4 NetU23_5 NetU24_4 NetU24_5 NetU25_4 NetU25_5 NTC1_N NTC1_P PWM_BUF_EN PWM_CLK_SD_DC_DELAYED PWM_SYNC_RX PWM_SYNC_TX RXCLK_5V RXD0_5V RXD1_5V SPIB_CLK SPIB_PICO SPIB_POCI SPIB_PTE TEMP1 TEMP2 TEMP3 TXCLK_5V TXD0_5V TXD1_5V
net class HV_DC_SN_N: 5V_ISO_SN_SENS DC_DS1 DC_G1 DC_KS1 I_HALL_N I_HALL_P I_SW_NEG I_SW_POS NetC2_1 NetC111_1 NetC115_1 NetC117_1 NetD15_1
net class HV_DC_N: DC_DAB DC_DS2 DC_DS4 DC_G2 DC_G4 DC_KS2 DC_KS4 NetJ11_1
component class "U_TIDA-011012 Switch Node Hall Current Sensing": C158 C159 C160 C162 R199 R202 R203 U25
component class "U_TIDA-011012 DC IV Sensing": C73 C74 C75 C76 C77 C78 C79 C80 C81 C82 C83 C84 C85 C86 C87 C88 C89 C90 C91 R151 R152 R153 R154 R158 R159 R160 R161 R162 R163 R164 R165 U6 U7 U8
component class U_TIDA-011012_Hardware: !PCB1 FID1 FID2 FID3 H2 H3 H4 H5 H6 H7 H8 H9 H10 H12 LBL1 Logo1 Logo3 Logo4 LOGO6 LOGO7 LOGO8 LOGO9 ZZ1 ZZ2 ZZ3 ZZ4
component class Label: LBL1
component class FiducialMark: FID1 FID2 FID3
component class AssemblyNote: ZZ1 ZZ2 ZZ3 ZZ4
component class "U_TIDA-011012 Optical Interface": C134 C135 C136 C137 C138 C139 C140 C141 C142 C143 C144 C145 C147 C148 C149 C150 C151 C152 L1 L2 L3 R193 R194 R195 R196 R197 R198 R208 R209 R210 R215 R216 R217 TP4 TP5 TP6 TP7 TP8 TP9 TP10 TP11 TP12 U19 U20 U21 U22 U23 U24 U26 U27 U28
component class "U_TIDA-011012 Fans and Temp Sense": C122 C123 C124 C125 C126 C127 C128 C129 C146 D33 H13 H14 J28 J29 Q2 R186 R187 R188 R189 R190 R218 U14 U15 U16 U29
component class "U_TIDA-011012 Communication": C27 C29 C30 C33 C34 C35 C40 C41 C43 C45 C46 C49 C50 C51 C52 C53 C153 C154 C155 D25 D26 D27 J17 J18 J19 R44 R45 R46 R47 R48 R49 R50 R53 R54 R55 R56 R57 R59 R61 R63 R66 R68 R69 R70 R71 R72 R73 R74 R77 R78 R82 R83 R85 R86 R87 R88 R90 R94 R100 R102 R104 R105 R106 R107 R108 R109 R111 R112 R114 R115 R116 R117 R118 R119 R120 R121 R122 R123 R125 R126 R127 R128 R129 R130 R131 R132 R133 R149 R150 R205 U2
component class "U_TIDA-011012 Current Comparator": C111 C112 C113 C114 C115 C116 C117 C118 C119 C120 C121 R181 R182 R183 R184 R185 U12 U13
component class "TIDA-011012-LV Power Conversion": C1 C2 C7 C8 C9 C11 C12 C13 C19 C20 C21 C23 C24 C25 C65 C71 C163 C164 C173 C174 C175 C176 C177 C178 C179 C180 C190 C191 C192 C193 C194 C195 C196 C197 C198 C199 D3 D4 D7 D8 D11 D12 D15 D16 D19 D20 D23 D24 H1 H11 H16 J3 J4 J5 J6 J9 J10 J11 J12 J15 J16 MD2 R3 R4 R7 R8 R11 R12 R15 R16 R19 R20 R22 R24 R28 R29 R30 R32 R34 R36 R38 R40 R41 R43 R200 R201 R206 R207 R211 R212 R213 R214 TP13 TP14 TP15 TP16 TP18 TP20
component class Header: J19 J20 J22 J23
component class "U_TIDA-011012 Auxiliary Power": C10 C22 C55 C56 C57 C58 C59 C60 C61 C62 C63 C64 C66 C67 C68 C69 C70 C72 C169 C170 C171 C172 D29 D30 D31 D32 J20 J21 J22 J23 J24 J25 J26 J27 L7 Q1 R134 R135 R136 R137 R138 R139 R140 R141 R142 R143 R144 R145 R146 R147 R148 TP1 TP2 TP3 TP21 TP22 TP23 U3 U4 U5
component class "Mounting Holes": H1 H2 H3 H4 H5 H6 H7 H8 H9 H10 H11 H12 H13 H14 H16

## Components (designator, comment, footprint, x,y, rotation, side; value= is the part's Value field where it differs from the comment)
C1 "C4ASMBW4200A3HJ" FP-C4ASMBW4200A3HJ_RADIAL-MFG 182,231 r180 top value=2µF
C2 "C4ASMBW4200A3HJ" FP-C4ASMBW4200A3HJ_RADIAL-MFG 229,120 r180 top value=2µF
C7 "C4AQJBW5550M3MJ" FP-C4AQJBW5550M3MJ_PTH_CAP_57MM5_30MM0-MFG 64.5,249.5 r90 top value=55µF
C8 "C4AQJBW5550M3MJ" FP-C4AQJBW5550M3MJ_PTH_CAP_57MM5_30MM0-MFG 96.65,249.5 r90 top value=55µF
C9 "C4AQJBW5550M3MJ" FP-C4AQJBW5550M3MJ_PTH_CAP_57MM5_30MM0-MFG 128.65,249.5 r90 top value=55µF
C10 "CL10B104KA8VPJC" FP-CL10B104KA8VPJC_0603-MFG 35,60 r0 bottom value=100nF
C11 "C2220X103KHRAC7800" FP-C2220X103KHRAC7800_2220-MFG 151,134 r0 bottom value=10nF
C12 "C2220X103KHRAC7800" FP-C2220X103KHRAC7800_2220-MFG 99,68 r180 bottom value=10nF
C13 "C2220X103KHRAC7800" FP-C2220X103KHRAC7800_2220-MFG 99,62 r180 bottom value=10nF
C19 "C4AQJBW5550M3MJ" FP-C4AQJBW5550M3MJ_PTH_CAP_57MM5_30MM0-MFG 64.5,190.5 r90 top value=55µF
C20 "C4AQJBW5550M3MJ" FP-C4AQJBW5550M3MJ_PTH_CAP_57MM5_30MM0-MFG 96.5,190.5 r90 top value=55µF
C21 "C4AQJBW5550M3MJ" FP-C4AQJBW5550M3MJ_PTH_CAP_57MM5_30MM0-MFG 128.65,190.5 r90 top value=55µF
C22 "CL10B104KA8VPJC" FP-CL10B104KA8VPJC_0603-MFG 42.781,32.606 r90 bottom value=100nF
C23 "C2220X103KHRAC7800" FP-C2220X103KHRAC7800_2220-MFG 151,140 r0 bottom value=10nF
C24 "C2220X103KHRAC7800" FP-C2220X103KHRAC7800_2220-MFG 92,56 r0 bottom value=10nF
C25 "C2220X103KHRAC7800" FP-C2220X103KHRAC7800_2220-MFG 93,125 r180 bottom value=10nF
C27 "C0603X221K5RACTU" 0603 150.692,19.539 r90 top value=220pF
C29 "C0603X221K5RACTU" 0603 147.592,19.539 r90 top value=220pF
C30 "C0603X221K5RACTU" 0603 124.89,4.783 r270 top value=220pF
C33 "C0603X221K5RACTU" 0603 123.114,4.783 r270 top value=220pF
C34 "C0603X221K5RACTU" 0603 144.492,19.539 r90 top value=220pF
C35 "C0603X221K5RACTU" 0603 121.338,4.783 r270 top value=220pF
C40 "C0603X221K5RACTU" 0603 141.442,19.539 r90 top value=220pF
C41 "C0603X221K5RACTU" 0603 119.562,4.783 r270 top value=220pF
C43 "C0603X221K5RACTU" 0603 117.787,4.783 r270 top value=220pF
C45 "GMC10X7R104K25NT" FP-GMC10X7R104K25NT_0603-MFG 87,30 r180 bottom value=100nF
C46 "C0603X221K5RACTU" 0603 116.011,4.783 r270 top value=220pF
C49 "C0603X221K5RACTU" 0603 77.063,38.818 r0 bottom value=220pF
C50 "C0603X221K5RACTU" 0603 77.063,33.562 r0 bottom value=220pF
C51 "C0603X221K5RACTU" 0603 90.35,38.818 r180 bottom value=220pF
C52 "C0603X221K5RACTU" 0603 90.35,33.638 r180 bottom value=220pF
C53 "C0603X221K5RACTU" 0603 95,32 r90 bottom value=220pF
C55 "16ZLJ1000MCE10X16" CAPPR5-10x16 7,48 r180 top value=1000uF
C56 "16ZLJ1000MCE10X16" CAPPR5-10x16 7,36 r180 top value=1000uF
C57 "C1608X7R1V105K080AC" 0603 35,62 r0 bottom value=1uF
C58 "06033C104JAT2A" 0603 30.65,25.087 r270 bottom value=0.1uF
C59 "C1608X7R1V105K080AC" 0603 32.449,54.019 r180 bottom value=1uF
C60 "GRM188R72A272KA01D" 0603 30,60 r180 bottom value=2700pF
C61 "C0603X332K5RACTU" 0603 30,56 r180 bottom value=3300pF
C62 "GRM155R71E104KE14D" 0402L 43,50 r0 bottom value=0.1uF
C63 "GRM1885C2A220JA01D" 0603 30.65,30.087 r270 bottom value=22pF
C64 "EMK107BB7225KA-T" 0603 40.781,32.606 r90 bottom value=2.2uF
C65 "C2220X103KHRAC7800" FP-C2220X103KHRAC7800_2220-MFG 93,131 r180 bottom value=10nF
C66 "EMK107BB7225KA-T" 0603 49,33 r90 bottom value=2.2uF
C67 "GRM21BZ71A226ME15L" 0805_HV 33.646,20.956 r180 bottom value=22uF
C68 "GRM21BZ71A226ME15L" 0805_HV 33.65,23.087 r180 bottom value=22uF
C69 "GRM21BZ71A226ME15L" 0805_HV 33.635,18.757 r180 bottom value=22uF
C70 "EMK212BB7106KG-T" 0805_HV 33.649,38.565 r180 bottom value=10uF
C71 "C2220X103KHRAC7800" FP-C2220X103KHRAC7800_2220-MFG 99,56 r180 bottom value=10nF
C72 "EMK212BB7106KG-T" 0805_HV 33.644,36.397 r180 bottom value=10uF
C73 "CL10B104KA8VPJC" FP-CL10B104KA8VPJC_0603-MFG 28.66,131.232 r180 bottom value=100nF
C74 "CC0603KRX7R7BB225" 0603 28.52,129.175 r180 bottom value=2.2uF
C75 "CL10B104KA8VPJC" FP-CL10B104KA8VPJC_0603-MFG 28,147 r180 bottom value=100nF
C76 "CC0603KRX7R7BB225" 0603 27.945,148.649 r180 bottom value=2.2uF
C77 "C0603C103J3GAC7867" FP-C0603C103J3GAC7867_0603-MFG 31.483,147.313 r180 bottom value=10nF
C78 "0603ZC100KAT2A" 0603 110.867,19.275 r270 bottom value=10pF
C79 "0603ZC102KAT2A" FP-0603ZC102KAT2A_0603-MFG 29.721,151.973 r270 bottom value=1nF
C80 "0603ZC102KAT2A" FP-0603ZC102KAT2A_0603-MFG 36.507,151.973 r270 bottom value=1nF
C81 "C0603X221K5RACTU" 0603 42.641,125.125 r180 bottom value=220pF
C82 "CL10B104KA8VPJC" FP-CL10B104KA8VPJC_0603-MFG 45.299,131.885 r180 bottom value=100nF
C83 "CC0603KRX7R7BB225" 0603 45.208,130.206 r180 bottom value=2.2uF
C84 "CL10B104KA8VPJC" FP-CL10B104KA8VPJC_0603-MFG 45,147 r180 bottom value=100nF
C85 "CC0603KRX7R7BB225" 0603 44.538,149.003 r180 bottom value=2.2uF
C86 "06031C101JAT2A" FP-06031C101JAT2A_0603-MFG 47.986,147.313 r180 bottom value=100pF
C87 "0603ZC100KAT2A" 0603 107.463,19.275 r270 bottom value=10pF
C88 "MA0805XR106K160" FP-MA0805XR106K160_0805-IPC_C 40.844,130.453 r0 bottom value=10µF
C89 "GRT21BD71A226ME13L" FP-GRT21BD71A226ME13L_0805-MFG 40.058,148.308 r180 bottom value=22µF
C90 "C0603C153K5RACTU" FP-C0603C153K5RACTU_0603-IPC_A 40.818,132.572 r180 bottom
C91 "C0603C153K5RACTU" FP-C0603C153K5RACTU_0603-IPC_A 40.1,146.77 r0 bottom
C111 "CL10B104KA8VPJC" FP-CL10B104KA8VPJC_0603-MFG 153.122,68.012 r90 bottom value=100nF
C112 "CC0603KRX7R7BB225" 0603 151.466,67.993 r90 bottom value=2.2uF
C113 "CL10B104KA8VPJC" FP-CL10B104KA8VPJC_0603-MFG 152.623,51.349 r180 bottom value=100nF
C114 "CC0603KRX7R7BB225" 0603 152.407,49.459 r180 bottom value=2.2uF
C115 "C0603C274K8RACTU" 0603 154.8,67.947 r90 bottom value=0.27uF
C116 "0603ZC100KAT2A" 0603 155.184,50 r90 bottom value=10pF
C117 "CL10B104KA8VPJC" FP-CL10B104KA8VPJC_0603-MFG 157.245,67 r0 bottom value=100nF
C118 "GRT21BD71A226ME13L" FP-GRT21BD71A226ME13L_0805-MFG 145.323,68.482 r180 bottom value=22µF
C119 "MA0805XR106K160" FP-MA0805XR106K160_0805-IPC_C 145.634,50.446 r0 bottom value=10µF
C120 "C0603C153K5RACTU" FP-C0603C153K5RACTU_0603-IPC_A 145.115,66.635 r0 bottom
C121 "C0603C153K5RACTU" FP-C0603C153K5RACTU_0603-IPC_A 145.618,52.485 r180 bottom
C122 "UWT1E101MCL1GS" UWT_630x770 194,47 r180 bottom value=100uF
C123 "CL10B104KA8VPJC" FP-CL10B104KA8VPJC_0603-MFG 19.905,22.357 r180 bottom value=100nF
C124 "06031C101JAT2A" FP-06031C101JAT2A_0603-MFG 18,19 r270 bottom value=100pF
C125 "CL10B104KA8VPJC" FP-CL10B104KA8VPJC_0603-MFG 16.594,22.357 r0 bottom value=100nF
C126 "CL10B104KA8VPJC" FP-CL10B104KA8VPJC_0603-MFG 145.267,36 r90 bottom value=100nF
C127 "06031C101JAT2A" FP-06031C101JAT2A_0603-MFG 141.565,38.157 r180 bottom value=100pF
C128 "CL10B104KA8VPJC" FP-CL10B104KA8VPJC_0603-MFG 145.213,39.057 r270 bottom value=100nF
C129 "CL10B104KA8VPJC" FP-CL10B104KA8VPJC_0603-MFG 130,42 r270 bottom value=100nF
C134 "C0603C820K5GACTU" 0603 231,16 r0 bottom value=82pF
C135 "GMC10X7R104K25NT" FP-GMC10X7R104K25NT_0603-MFG 241.175,16 r180 bottom value=100nF
C136 "C0603C820K5GACTU" 0603 203,18 r0 bottom value=82pF
C137 "GMC10X7R104K25NT" FP-GMC10X7R104K25NT_0603-MFG 162.25,10 r180 bottom value=100nF
C138 "GMC10X7R104K25NT" FP-GMC10X7R104K25NT_0603-MFG 215,16 r180 bottom value=100nF
C139 "C0603C820K5GACTU" 0603 176,18 r0 bottom value=82pF
C140 "GMC10X7R104K25NT" FP-GMC10X7R104K25NT_0603-MFG 187,16 r180 bottom value=100nF
C141 "GMC10X7R104K25NT" FP-GMC10X7R104K25NT_0603-MFG 180,27 r180 bottom value=100nF
C142 "GMC10X7R104K25NT" FP-GMC10X7R104K25NT_0603-MFG 181,34 r180 bottom value=100nF
C143 "GMC10X7R104K25NT" FP-GMC10X7R104K25NT_0603-MFG 170,23 r180 bottom value=100nF
C144 "GMC10X7R104K25NT" FP-GMC10X7R104K25NT_0603-MFG 171,29 r180 bottom value=100nF
C145 "GMC10X7R104K25NT" FP-GMC10X7R104K25NT_0603-MFG 161.425,4 r180 bottom value=100nF
C146 "CL10B104KA8VPJC" FP-CL10B104KA8VPJC_0603-MFG 192,32 r180 bottom value=100nF
C147 "0603ZC100KAT2A" 0603 177,33.2 r90 bottom value=10pF
C148 "0603ZC100KAT2A" 0603 183,28 r270 bottom value=10pF
C149 "0603ZC100KAT2A" 0603 167,28 r90 bottom value=10pF
C150 "0603ZC100KAT2A" 0603 173,23 r270 bottom value=10pF
C151 "0603ZC100KAT2A" 0603 158.25,9.2 r90 bottom value=10pF
C152 "0603ZC100KAT2A" 0603 164.891,4.522 r270 bottom value=10pF
C153 "0603ZC100KAT2A" 0603 130.463,10.525 r90 bottom value=10pF
C154 "0603ZC100KAT2A" 0603 128.5,10.525 r90 bottom value=10pF
C155 "0603ZC100KAT2A" 0603 126.569,10.525 r90 bottom value=10pF
C158 "CL10B105KA8VPJC" FP-CL10B105KA8VPJC_0603-MFG 171,62 r0 bottom value=1µF
C159 "06033C104KAT2A" 0603 171.193,64 r180 bottom value=0.1uF
C160 "C1608C0G2A392J080AE" 0603 181,63 r90 bottom value=3900pF
C162 "C1608C0G2A392J080AE" 0603 175,64 r180 bottom value=3900pF
C163 "C2220X103KHRAC7800" FP-C2220X103KHRAC7800_2220-MFG 93,137 r180 bottom value=10nF
C164 "C2220X103KHRAC7800" FP-C2220X103KHRAC7800_2220-MFG 92,62 r0 bottom value=10nF
C169 "EMK212BB7106KG-T" 0805_HV 33.649,34.194 r180 bottom value=10uF
C170 "EMK212BB7106KG-T" 0805_HV 33.65,32.087 r180 bottom value=10uF
C171 "06033C104JAT2A" 0603 33.65,30.087 r0 bottom value=0.1uF
C172 "C0603C103K4RACTU" 0603 27.65,26.087 r180 bottom value=0.01uF
C173 "C4ASMBW4200A3HJ" FP-C4ASMBW4200A3HJ_RADIAL-MFG 182,177 r180 top value=2µF
C174 "C4ASMBW4200A3HJ" FP-C4ASMBW4200A3HJ_RADIAL-MFG 218.1,256.75 r90 top value=2µF
C175 "C4ASMBW4200A3HJ" FP-C4ASMBW4200A3HJ_RADIAL-MFG 182,257 r180 top value=2µF
C176 "C4ASMBW4200A3HJ" FP-C4ASMBW4200A3HJ_RADIAL-MFG 182,204 r180 top value=2µF
C177 "C4ASMBW4200A3HJ" FP-C4ASMBW4200A3HJ_RADIAL-MFG 229,181 r180 top value=2µF
C178 "C4ASMBW4200A3HJ" FP-C4ASMBW4200A3HJ_RADIAL-MFG 229,156 r180 top value=2µF
C179 "C4ASMBW4200A3HJ" FP-C4ASMBW4200A3HJ_RADIAL-MFG 229,51 r180 top value=2µF
C180 "C4ASMBW4200A3HJ" FP-C4ASMBW4200A3HJ_RADIAL-MFG 229,86 r180 top value=2µF
C190 "C2220X103KHRAC7800" FP-C2220X103KHRAC7800_2220-MFG 100,137 r180 bottom value=10nF
C191 "C2220X103KHRAC7800" FP-C2220X103KHRAC7800_2220-MFG 100,131 r180 bottom value=10nF
C192 "C2220X103KHRAC7800" FP-C2220X103KHRAC7800_2220-MFG 100,125 r180 bottom value=10nF
C193 "C2220X103KHRAC7800" FP-C2220X103KHRAC7800_2220-MFG 144,140 r0 bottom value=10nF
C194 "C2220X103KHRAC7800" FP-C2220X103KHRAC7800_2220-MFG 144,134 r0 bottom value=10nF
C195 "C2220X103KHRAC7800" FP-C2220X103KHRAC7800_2220-MFG 106,56 r180 bottom value=10nF
C196 "C2220X103KHRAC7800" FP-C2220X103KHRAC7800_2220-MFG 106,62 r180 bottom value=10nF
C197 "C2220X103KHRAC7800" FP-C2220X103KHRAC7800_2220-MFG 106,68 r180 bottom value=10nF
C198 "C2220X103KHRAC7800" FP-C2220X103KHRAC7800_2220-MFG 85,62 r0 bottom value=10nF
C199 "C2220X103KHRAC7800" FP-C2220X103KHRAC7800_2220-MFG 85,56 r0 bottom value=10nF
D3 "STTH112A" SMA 83.057,73.977 r180 bottom value=1200V
D4 "STTH112A" SMA 82.957,115 r180 bottom value=1200V
D7 "STTH112A" SMA 77,75.977 r90 bottom value=1200V
D8 "STTH112A" SMA 76.7,112.323 r270 bottom value=1200V
D11 "STTH112A" SMA 77,83.84 r90 bottom value=1200V
D12 "STTH112A" SMA 76.7,104.786 r270 bottom value=1200V
D15 "STTH112A" SMA 128.043,74 r0 bottom value=1200V
D16 "STTH112A" SMA 127.943,115.023 r0 bottom value=1200V
D19 "STTH112A" SMA 134.3,76.677 r90 bottom value=1200V
D20 "STTH112A" SMA 134,113.023 r270 bottom value=1200V
D23 "STTH112A" SMA 134.3,84.214 r90 bottom value=1200V
D24 "STTH112A" SMA 134,105.16 r270 bottom value=1200V
D25 "LSL29K-G1H2-1-Z" FP-LSL29K-G1H2-1-Z_0603-0 70.163,19.402 r90 bottom
D26 "150060VS75000" WL-SMCW_GREEN 72.428,19.443 r90 bottom value=Green
D27 "150060VS75000" WL-SMCW_GREEN 74.412,19.407 r90 bottom value=Green
D29 "150060VS75000" WL-SMCW_GREEN 36.701,47.517 r180 bottom value=Green
D30 "B330A-13-F" SMA 31,51 r180 bottom value=30V
D31 "150060VS75000" WL-SMCW_GREEN 34.65,16.089 r90 bottom value=Green
D32 "150060VS75000" WL-SMCW_GREEN 51,33 r270 bottom value=Green
D33 "SBR0560S1-7" SOD-123 195,42 r180 bottom value=60V
FID1 "Fiducial" Fiducial10-20 229.762,25.711 r270 bottom
FID2 "Fiducial" Fiducial10-20 47.673,6.404 r90 bottom
FID3 "Fiducial" Fiducial10-20 51,4 r270 top
H1 "NY PMS 440 0025 PH" "NY PMS 440 0025 PH" 228,138 r180 bottom
H2 "NY PMS 440 0025 PH" "NY PMS 440 0025 PH" 35,220 r180 bottom
H3 "NY PMS 440 0025 PH" "NY PMS 440 0025 PH" 5,275 r180 bottom
H4 "NY PMS 440 0025 PH" "NY PMS 440 0025 PH" 245,230 r180 bottom
H5 "NY PMS 440 0025 PH" "NY PMS 440 0025 PH" 160,110 r180 bottom
H6 "NY PMS 440 0025 PH" "NY PMS 440 0025 PH" 5,92 r180 bottom
H7 "NY PMS 440 0025 PH" "NY PMS 440 0025 PH" 156,275 r180 bottom
H8 "NY PMS 440 0025 PH" "NY PMS 440 0025 PH" 245,22 r180 bottom
H9 "NY PMS 440 0025 PH" "NY PMS 440 0025 PH" 35,275 r180 bottom
H10 "NY PMS 440 0025 PH" "NY PMS 440 0025 PH" 19,132 r180 bottom locked
H11 "NY PMS 440 0025 PH" "NY PMS 440 0025 PH" 5,5 r180 top
H12 "NY PMS 440 0025 PH" "NY PMS 440 0025 PH" 245,275 r180 bottom
H13 "NY PMS 440 0025 PH" "NY PMS 440 0025 PH" 19,37 r0 bottom locked
H14 "NY PMS 440 0025 PH" "NY PMS 440 0025 PH" 159,37 r90 bottom
H16 "NY PMS 440 0025 PH" "NY PMS 440 0025 PH" 159,152 r180 bottom
J3 "HLE-103-02-G-DV" Samtec_HLE-103-02-x-DV 84.1,85.5 r270 bottom
J4 "HLE-103-02-G-DV" Samtec_HLE-103-02-x-DV 84.1,103.5 r90 bottom
J5 "7461086" Wurth_7461086 6,255 r90 bottom
J6 "7461086" Wurth_7461086 244,204 r90 bottom
J9 "HLE-103-02-G-DV" Samtec_HLE-103-02-x-DV 126.9,85.5 r270 bottom
J10 "HLE-103-02-G-DV" Samtec_HLE-103-02-x-DV 126.9,103.5 r90 bottom
J11 "7461086" Wurth_7461086 6,185 r90 bottom
J12 "7461086" Wurth_7461086 243.41,68.477 r90 bottom
J15 "HLE-105-02-G-DV-BE-A" FP-HLE-105-02-G-DV-BE-A_CONN_RCPT_10-MFG 105.45,148.9 r180 bottom
J16 "HLE-105-02-G-DV-BE-A" FP-HLE-105-02-G-DV-BE-A_CONN_RCPT_10-MFG 105.55,40.1 r0 bottom
J17 "HSEC8-160-01-L-DV-A-BL" controlCARD-120HSEC 130.71,12.584 r180 top locked
J18 "HSEC8-130-01-L-DV-A" controlCARD-180HSEC-60pinAddon 70.999,12.606 r180 top locked
J19 "61301011121" Wurth_61301011121 71.319,2.976 r0 top
J20 "TSM-102-01-T-SV-P-TR" Samtec_TSM-102-01-T-SV-P-TR 42,43 r270 bottom
J21 "PJ-002AH-SMT-TR" CUI_PJ-002AH-SMT 38,8.05 r90 top
J22 "TSM-102-01-T-SV-P-TR" Samtec_TSM-102-01-T-SV-P-TR 35,43 r270 bottom
J23 "TSM-102-01-T-SV-P-TR" Samtec_TSM-102-01-T-SV-P-TR 44,20 r0 bottom
J24 "HLE-103-02-G-DV" Samtec_HLE-103-02-x-DV 13.5,151.5 r180 bottom
J25 "HLE-103-02-G-DV" Samtec_HLE-103-02-x-DV 61.5,151.5 r180 bottom
J26 "HLE-103-02-G-DV" Samtec_HLE-103-02-x-DV 9.5,65.5 r180 bottom
J27 "HLE-103-02-G-DV" Samtec_HLE-103-02-x-DV 69.5,65.5 r180 bottom
J28 "0022111031" FP-0022111031_HDR3-MFG 200,25.7 r0 top
J29 "0022111031" FP-0022111031_HDR3-MFG 200,33.7 r0 top
L1 "NLFV25T-470K-PF" NLCV25 238.42,16.947 r270 bottom value=47uH
L2 "NLFV25T-470K-PF" NLCV25 214.577,19.03 r270 bottom value=47uH
L3 "NLFV25T-470K-PF" NLCV25 186,19 r270 bottom value=47uH
L7 "74439324047" FP-74439324047_SMD2-MFG 38.65,25.749 r270 bottom value=4.7uH
LBL1 "THT-14-423-10" Label_650x200 179,118 r90 bottom
Logo1 "CE Mark" CE_Mark_5mm 6,127 r270 bottom
Logo3 "FCC disclaimer" FCC_disclaimer 12,116 r90 bottom
Logo4 "WEEE logo" WEEE_Minimum 5,118 r270 bottom
LOGO6 "CAUTION HOT SURFACE" IEC_HotSurface_Medium 149,258 r180 bottom
LOGO7 "DANGER HIGH VOLTAGE" IEC_HighVoltage_Medium 149,238 r180 bottom
LOGO8 "CAUTION HOT SURFACE" IEC_HotSurface_Medium 36,242 r270 top
LOGO9 "DANGER HIGH VOLTAGE" IEC_HighVoltage_Medium 35,258 r270 top
MD2 "G4H22MT33GB4" FP-G4H22MT33GB4_SiCPAK-G+_MODIFIED-MFG 105.5,94.5 r270 top locked
Q1 "CSD17571Q2" DQK0006C 43.653,48.014 r0 bottom value=30V
Q2 "DMN3042L-13" FP-DMN3042L-13_SOT23-MFG 191.704,38.85 r0 bottom
R3 "RC1206FR-07120KL" 1206 106.592,268.8 r90 bottom value=120k
R4 "RC1206FR-07120KL" 1206 106.592,247.971 r270 bottom value=120k
R7 "RC1206FR-07120KL" 1206 106.592,263.593 r90 bottom value=120k
R8 "RC1206FR-07120KL" 1206 106.592,242.764 r270 bottom value=120k
R11 "RC1206FR-07120KL" 1206 106.592,258.386 r90 bottom value=120k
R12 "RC1206FR-07120KL" 1206 106.592,237.557 r270 bottom value=120k
R15 "RC1206FR-07120KL" 1206 106.592,253.179 r90 bottom value=120k
R16 "RC1206FR-07120KL" 1206 106.592,232.35 r270 bottom value=120k
R19 "ERJ-3EKF1002V" 0603 91.1,88.7 r0 bottom value=10.0k
R20 "ERJ-3EKF1002V" 0603 91.1,100.3 r0 bottom value=10.0k
R22 "RC1206FR-07120KL" 1206 106.592,210.32 r270 bottom value=120k
R24 "RC1206FR-07120KL" 1206 106.592,187.851 r90 bottom value=120k
R28 "RC1206FR-07120KL" 1206 106.592,204.703 r270 bottom value=120k
R29 "ERJ-3EKF1002V" 0603 119.9,88.7 r180 bottom value=10.0k
R30 "ERJ-3EKF1002V" 0603 119.9,100.3 r180 bottom value=10.0k
R32 "RC1206FR-07120KL" 1206 106.592,182.234 r90 bottom value=120k
R34 "RC1206FR-07120KL" 1206 106.592,199.086 r270 bottom value=120k
R36 "RC1206FR-07120KL" 1206 106.592,176.617 r90 bottom value=120k
R38 "RC1206FR-07120KL" 1206 106.592,193.469 r270 bottom value=120k
R40 "RC1206FR-07120KL" 1206 106.592,171 r90 bottom value=120k
R41 "WSL4026L5000FEB" WSL4026_0p5milli 33.346,159.313 r0 bottom value=0.0005
R43 "WSL4026L5000FEB" WSL4026_0p5milli 155.355,77.253 r0 bottom value=0.0005
R44 "ERJ-3GEYJ470V" 0603 150.688,23.409 r270 top value=47
R45 "ERJ-3EKF1002V" 0603 64.066,22.477 r90 bottom value=10.0k
R46 "ERJ-3EKF1002V" 0603 65.898,22.507 r90 bottom value=10.0k
R47 "ERJ-3EKF1002V" 0603 68,22.507 r90 bottom value=10.0k
R48 "CRCW0603499RFKEAC" 0603 72.427,22.447 r90 bottom value=499
R49 "CRCW0603499RFKEAC" 0603 70.111,22.406 r90 bottom value=499
R50 "CRCW0603499RFKEAC" 0603 74.411,22.405 r90 bottom value=499
R53 "ERJ-3EKF1002V" 0603 64.066,18.507 r90 bottom value=10.0k
R54 "ERJ-3EKF1002V" 0603 65.898,18.507 r90 bottom value=10.0k
R55 "ERJ-3EKF1002V" 0603 68,18.507 r90 bottom value=10.0k
R56 "ERJ-3GEYJ470V" 0603 147.588,23.409 r270 top value=47
R57 "ERJ-3GEYJ470V" 0603 124.825,10.525 r90 bottom value=47
R59 "ERJ-H3G0R00V" FP-ERJ-H3G0R00V_0603-MFG 139,7 r0 top value=0
R61 "ERJ-H3G0R00V" FP-ERJ-H3G0R00V_0603-MFG 139,5 r0 top value=0
R63 "ERJ-H3G0R00V" FP-ERJ-H3G0R00V_0603-MFG 135.315,5.221 r270 top value=0
R66 "ERJ-H3G0R00V" FP-ERJ-H3G0R00V_0603-MFG 133.539,5.221 r270 top value=0
R68 "ERJ-3GEYJ470V" 0603 122.862,10.525 r90 bottom value=47
R69 "ERJ-H3G0R00V" FP-ERJ-H3G0R00V_0603-MFG 131.764,5.221 r270 top value=0
R70 "ERJ-H3G0R00V" FP-ERJ-H3G0R00V_0603-MFG 127.888,19.858 r270 top value=0
R71 "ERJ-H3G0R00V" FP-ERJ-H3G0R00V_0603-MFG 129.988,5.221 r270 top value=0
R72 "ERJ-H3G0R00V" FP-ERJ-H3G0R00V_0603-MFG 126.444,19.858 r270 top value=0
R73 "ERJ-H3G0R00V" FP-ERJ-H3G0R00V_0603-MFG 128.212,5.221 r270 top value=0
R74 "ERJ-H3G0R00V" FP-ERJ-H3G0R00V_0603-MFG 126.436,5.221 r270 top value=0
R77 "ERJ-3GEYJ470V" 0603 144.488,23.409 r270 top value=47
R78 "ERJ-3GEYJ470V" 0603 120.899,10.525 r90 bottom value=47
R82 "ERJ-H3G0R00V" FP-ERJ-H3G0R00V_0603-MFG 120.594,19.769 r270 top value=0
R83 "ERJ-H3G0R00V" FP-ERJ-H3G0R00V_0603-MFG 118.948,19.769 r270 top value=0
R85 "ERJ-3GEYJ470V" 0603 141.438,23.409 r270 top value=47
R86 "ERJ-3GEYJ470V" 0603 118.936,10.525 r90 bottom value=47
R87 "ERJ-H3G0R00V" FP-ERJ-H3G0R00V_0603-MFG 117.253,19.769 r270 top value=0
R88 "ERJ-H3G0R00V" FP-ERJ-H3G0R00V_0603-MFG 115.651,19.769 r270 top value=0
R90 "ERJ-H3G0R00V" FP-ERJ-H3G0R00V_0603-MFG 114.092,19.769 r270 top value=0
R94 "ERJ-3GEYJ470V" 0603 116.973,10.525 r90 bottom value=47
R100 "ERJ-H3G0R00V" FP-ERJ-H3G0R00V_0603-MFG 110.679,19.919 r270 top value=0
R102 "ERJ-H3G0R00V" FP-ERJ-H3G0R00V_0603-MFG 109.237,19.919 r270 top value=0
R104 "ERJ-H3G0R00V" FP-ERJ-H3G0R00V_0603-MFG 87,28 r180 bottom value=0
R105 "ERJ-H3G0R00V" FP-ERJ-H3G0R00V_0603-MFG 107.463,19.919 r270 top value=0
R106 "ERJ-H3G0R00V" FP-ERJ-H3G0R00V_0603-MFG 106,5 r0 top value=0
R107 "ERJ-H3G0R00V" FP-ERJ-H3G0R00V_0603-MFG 105.934,20 r270 top value=0
R108 "ERJ-H3G0R00V" FP-ERJ-H3G0R00V_0603-MFG 106,7 r0 top value=0
R109 "ERJ-3GEYJ470V" 0603 115.01,10.525 r90 bottom value=47
R111 "ERJ-3GEYJ470V" 0603 77.063,35.28 r180 bottom value=47
R112 "ERJ-3GEYJ470V" 0603 77.063,40.536 r180 bottom value=47
R114 "ERJ-3GEYJ470V" 0603 90.35,40.549 r0 bottom value=47
R115 "ERJ-3GEYJ470V" 0603 81,19.8 r270 top value=47
R116 "ERJ-H3G0R00V" FP-ERJ-H3G0R00V_0603-MFG 81,6.275 r90 top value=0
R117 "ERJ-3GEYJ470V" 0603 90.35,35.356 r0 bottom value=47
R118 "ERJ-3GEYJ470V" 0603 79.024,6.313 r270 top value=47
R119 "ERJ-H3G0R00V" FP-ERJ-H3G0R00V_0603-IPC_B 78.568,19.8 r90 top value=0
R120 "ERJ-3EKF1002V" 0603 77.063,37.099 r0 bottom value=10.0k
R121 "ERJ-3EKF1002V" 0603 77.063,31.842 r0 bottom value=10.0k
R122 "ERJ-3EKF1002V" 0603 90.35,37.099 r180 bottom value=10.0k
R123 "ERJ-3EKF1002V" 0603 90.35,31.924 r180 bottom value=10.0k
R125 "ERJ-H3G0R00V" FP-ERJ-H3G0R00V_0603-MFG 69.656,19.045 r90 top value=0
R126 "ERJ-H3G0R00V" FP-ERJ-H3G0R00V_0603-MFG 68.952,6.275 r90 top value=0
R127 "ERJ-H3G0R00V" FP-ERJ-H3G0R00V_0603-MFG 68.201,19.03 r90 top value=0
R128 "ERJ-H3G0R00V" FP-ERJ-H3G0R00V_0603-MFG 67.599,6.275 r90 top value=0
R129 "ERJ-H3G0R00V" FP-ERJ-H3G0R00V_0603-MFG 66.829,19.049 r90 top value=0
R130 "ERJ-H3G0R00V" FP-ERJ-H3G0R00V_0603-MFG 66.096,6.275 r90 top value=0
R131 "ERJ-H3G0R00V" FP-ERJ-H3G0R00V_0603-MFG 65.294,19.049 r90 top value=0
R132 "ERJ-H3G0R00V" FP-ERJ-H3G0R00V_0603-MFG 64.599,6.275 r90 top value=0
R133 "ERJ-H3G0R00V" FP-ERJ-H3G0R00V_0603-MFG 63.466,19.051 r90 top value=0
R134 "RC0603FR-07470KL" 0603 39.963,61.752 r90 bottom value=470k
R135 "RC0603FR-0747KL" 0603 36,53 r270 bottom value=47.0k
R136 "RC0603FR-071K1L" 0603 30,58 r0 bottom value=1.10k
R137 "RC0603FR-075K6L" 0603 38,53 r90 bottom value=5.60k
R138 "RC0603FR-0711KL" 0603 39.983,58.478 r90 bottom value=11.0k
R139 "RC0603FR-0747KL" 0603 36.81,49.356 r180 bottom value=47.0k
R140 "RC0603FR-072KL" 0603 40.27,47.532 r180 bottom value=2.00k
R141 "RC0603FR-0747KL" 0603 40,55 r90 bottom value=47.0k
R142 "RC0603FR-0715KL" 0603 41,52 r180 bottom value=15.0k
R143 "RC0603FR-0747KL" 0603 27.65,24.087 r180 bottom value=47.0k
R144 "RC0603FR-07220KL" 0603 28.98,30.071 r90 bottom value=220k
R145 "RG1608P-103-B-T5" 0603 27.65,22.087 r180 bottom value=10.0k
R146 "RC0603FR-0730KL" 0603 27.271,30.06 r270 bottom value=30.0k
R147 "CRCW0603499RFKEAC" 0603 32.65,16.087 r270 bottom value=499
R148 "CRCW0603499RFKEAC" 0603 50,36 r0 bottom value=499
R149 "ERJ-3EKF1002V" 0603 118.027,4.983 r270 bottom value=10.0k
R150 "ERJ-3EKF1002V" 0603 116.014,4.983 r270 bottom value=10.0k
R151 "TNPW060310R0BEEA" 0603 32.173,151.973 r270 bottom value=10.0
R152 "TNPW060310R0BEEA" 0603 34.49,151.973 r270 bottom value=10.0
R153 "RC0603FR-0740R2L" 0603 32.008,126.875 r270 bottom value=40.2
R154 "RC0603FR-07100RL" 0603 45.236,126 r90 bottom value=100
R158 "CHV1206-FX-1504ELF" FP-CHV1206-FX-1504ELF_1206-MFG 51.5,255.109 r270 bottom value=1.5M
R159 "CHV1206-FX-1504ELF" FP-CHV1206-FX-1504ELF_1206-MFG 51.5,249.139 r270 bottom value=1.5M
R160 "CHV1206-FX-1504ELF" FP-CHV1206-FX-1504ELF_1206-MFG 51.5,200.5 r270 bottom value=1.5M
R161 "CHV1206-FX-1504ELF" FP-CHV1206-FX-1504ELF_1206-MFG 51.5,195.5 r270 bottom value=1.5M
R162 "CHV1206-FX-1504ELF" FP-CHV1206-FX-1504ELF_1206-MFG 51.5,190.5 r270 bottom value=1.5M
R163 "RC0603FR-0740R2L" 0603 48.536,130.728 r270 bottom value=40.2
R164 "RC0603FR-074K7L" 0603 48.2,149 r180 bottom value=4.70k
R165 "RC0603JR-0718KL" 0603 42,128 r180 bottom value=18k
R181 "TNPW060310R0BEEA" 0603 149.709,68.021 r270 bottom value=10.0
R182 "TNPW060310R0BEEA" 0603 153.914,71.276 r0 bottom value=10.0
R183 "RC0603FR-0740R2L" 0603 157,50 r270 bottom value=40.2
R184 "ERJ-3EKF1001V" 0603 157.475,68.709 r180 bottom value=1.00k
R185 "RC0603JR-0718KL" 0603 148.416,51.366 r270 bottom value=18k
R186 "ERJ-3GEYJ470V" 0603 16,19.2 r90 bottom value=47
R187 "RT0603BRD07200RL" 0603 186,38 r0 bottom value=200
R188 "CRCW060310K0JNEBC" FP-CRCW060310K0JNEBC_0603-MFG 189,39 r270 bottom value=10k
R189 "ERJ-3GEYJ470V" 0603 141.442,39.957 r0 bottom value=47
R190 "RC0603FR-07680RL" 0603 124,38 r0 bottom value=680
R193 "RC0603FR-07390RL" 0603 231,18 r180 bottom value=390
R194 "RC0603FR-07120RL" 0603 228,16.2 r270 bottom value=120
R195 "CRCW060347R0JNEA" 0603 244.8,16 r180 bottom value=47
R196 "RC0603FR-07390RL" 0603 203,16 r180 bottom value=390
R197 "RC0603FR-07120RL" 0603 200,16.8 r270 bottom value=120
R198 "CRCW060347R0JNEA" 0603 218,17 r90 bottom value=47
R199 "CRCW060368R1FKEA" 0603 179,63 r270 bottom value=68.1
R200 "CRCW12064R70JNEA" 1206 15.175,210.244 r90 bottom value=4.7
R201 "CRCW12064R70JNEA" 1206 12.175,210.244 r90 bottom value=4.7
R202 "RC0603JR-078K2L" 0603 175,60 r0 bottom value=8.2k
R203 "RC0603JR-071K2L" 0603 175,62 r180 bottom value=1.2k
R205 "ERJ-3EKF1002V" 0603 97,32 r90 bottom value=10.0k
R206 "CRCW12064R70JNEA" 1206 9.175,210.244 r90 bottom value=4.7
R207 "CRCW12064R70JNEA" 1206 6.175,210.244 r90 bottom value=4.7
R208 "RC0603FR-07390RL" 0603 176,16 r180 bottom value=390
R209 "RC0603FR-07120RL" 0603 173,16 r270 bottom value=120
R210 "CRCW060347R0JNEA" 0603 190,17 r90 bottom value=47
R211 "CRCW12064R70JNEA" 1206 150,225 r180 bottom value=4.7
R212 "CRCW12064R70JNEA" 1206 150,222 r180 bottom value=4.7
R213 "CRCW12064R70JNEA" 1206 150,219 r180 bottom value=4.7
R214 "CRCW12064R70JNEA" 1206 150,216 r180 bottom value=4.7
R215 "ERJ-H3G0R00V" FP-ERJ-H3G0R00V_0603-MFG 177,29 r0 bottom value=0
R216 "ERJ-H3G0R00V" FP-ERJ-H3G0R00V_0603-MFG 167,25 r0 bottom value=0
R217 "ERJ-H3G0R00V" FP-ERJ-H3G0R00V_0603-MFG 158.25,6 r0 bottom value=0
R218 "ERJ-H3G0R00V" FP-ERJ-H3G0R00V_0603-MFG 122,43 r0 bottom value=0
TP1 "5010" Keystone5010 29,45 r180 bottom
TP2 "5011" Keystone5011 23,53 r180 bottom
TP3 "5010" Keystone5010 53,30 r180 bottom
TP4 "5122" Keystone5122 225,18 r180 bottom
TP5 "5122" Keystone5122 234.768,18.007 r180 bottom
TP6 "5122" Keystone5122 238.073,22.128 r180 bottom
TP7 "5122" Keystone5122 197,18 r180 bottom
TP8 "5122" Keystone5122 211,18 r180 bottom
TP9 "5122" Keystone5122 221,18 r180 bottom
TP10 "5122" Keystone5122 170,18 r180 bottom
TP11 "5122" Keystone5122 182.294,18.102 r180 bottom
TP12 "5122" Keystone5122 193,18 r180 bottom
TP13 "5122" Keystone5122 162,120 r180 bottom
TP14 "5010" Keystone5010 158,140 r180 bottom
TP15 "5122" Keystone5122 148,92 r180 bottom
TP16 "5122" Keystone5122 242,215 r180 bottom
TP18 "5011" Keystone5011 38,177 r180 bottom
TP20 "5122" Keystone5122 233,68 r180 bottom
TP21 "5011" Keystone5011 53,11 r180 bottom
TP22 "5011" Keystone5011 53,25 r180 bottom
TP23 "5011" Keystone5011 163,18 r270 bottom
U2 "SN74HCS126DR" D0014A-MFG 83.625,35.981 r0 bottom
U3 "TPS259474LRPWT" RPW0010A-MFG 34.25,57 r180 bottom
U4 "TLV75533PDBVR" DBV0005A_N 46,33 r0 bottom
U5 "TPS563203DRLR" DRL0006A-MFG 33.65,27.087 r180 bottom
U6 "AMC0306M05-Q1" DWV0008A-MFG 31.366,139.313 r270 bottom
U7 "AMC1336DWVR" DWV0008A 47.901,139.463 r270 bottom
U8 "UCC33421DHAR" DHA0016A-MFG 40.366,139.513 r90 bottom
U12 "AMC23C12DWVR" DWV0008A-MFG 155.465,58.95 r270 bottom
U13 "UCC33421DHAR" DHA0016A-MFG 145.115,59.557 r90 bottom
U14 "ISOTMP35BEDFQRQ1" DFQ0007A-MFG 18,27 r90 bottom
U15 "ISOTMP35BEDFQRQ1" DFQ0007A-MFG 150,37 r0 bottom
U16 "TLV9001IDBVR" DBV0005A_N 127.02,40.552 r90 bottom
U19 "TOTX1350(F)" FP-TOTX1350(F)_REC_OPT_PTH-MFG 229.248,7.151 r180 top
U20 "TORX1350A(F)" FP-TORX1350A(F)_OPTIC_RECIEVER_13MM0_13MM5-MFG 242.939,7.176 r180 top
U21 "TOTX1350(F)" FP-TOTX1350(F)_REC_OPT_PTH-MFG 201.829,7.151 r180 top
U22 "TORX1350A(F)" FP-TORX1350A(F)_OPTIC_RECIEVER_13MM0_13MM5-MFG 215.52,7.176 r180 top
U23 "TOTX1350(F)" FP-TOTX1350(F)_REC_OPT_PTH-MFG 174.411,7.151 r180 top
U24 "TORX1350A(F)" FP-TORX1350A(F)_OPTIC_RECIEVER_13MM0_13MM5-MFG 188.101,7.176 r180 top
U25 "TMCS1133B1QDVGR" DVG0010A-MFG 176.5,72.122 r270 bottom
U26 "TXU0202DCU" DCU0008A-MFG 179.75,30.55 r90 bottom
U27 "TXU0202DCU" DCU0008A-MFG 170,26 r90 bottom
U28 "TXU0202DCU" DCU0008A-MFG 161.25,7 r90 bottom
U29 "SN74LV1T34DBVR" DBV0005A_N 191.199,35.014 r0 bottom
ZZ1 "This Assembly Note is for PCB labels only" AssemblyNoteLabel 344.87,149.396 r90 top
ZZ2 "These assemblies are ESD sensitive, ESD precautions shall be observed." AssemblyNote 341.07,212.096 r90 top
ZZ3 "These assemblies must be clean and free from flux and all contaminants. Use of no clean flux is not acceptable." AssemblyNote 337.27,172.696 r90 top
ZZ4 "These assemblies must comply with workmanship standards IPC-A-610 Class 2, unless otherwise specified." AssemblyNote 333.47,180.996 r90 top

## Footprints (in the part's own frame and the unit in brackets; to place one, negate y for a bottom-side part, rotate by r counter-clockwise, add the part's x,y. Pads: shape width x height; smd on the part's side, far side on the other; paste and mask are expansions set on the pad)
0402L [mm] "0402 from SM-752 data"
  rect 0.6x0.5 smd: 1(-0.5,0) 2(0.5,0)
  body extent -0.55,-0.3 0.55,0.3, height 0.6
0603 [mm] "0603 from SM-752 data"
  rect 1x0.95 smd: 1(-0.8,0) 2(0.8,0)
  silkscreen extent -1.52,-0.69 1.52,0.69, body extent -0.87,-0.47 0.87,0.47, height 1
0805_HV [mil] "0805 with 30mil clearance between pads"
  rect 50x63 smd: 1(-40,0) 2(40,0)
  silkscreen extent -74,-40 74,40, body extent -43,-29 43,29, height 57
1206 [mm] "1206 from SM-752 data"
  rect 1.3x1.85 smd: 1(-1.45,0) 2(1.45,0)
  silkscreen extent -2.4,-1.21 2.4,1.21, body extent -1.7,-0.9 1.7,0.9, height 1.35
AssemblyNote [mm] "Assembly Note"
AssemblyNoteLabel [mm] "Assembly Note for PCB Labels"
CAPPR5-10x16 [mm] "Capacitor, Electrolytic, Radial; Body 10 x 16 mm (Dia.xH typ); Pin Spacing 5 mm (typ)"
  rect 1.5x1.5 hole 0.9: 1(-2.5,0)
  round 1.5 hole 0.9: 2(2.5,0)
  silkscreen extent -5,-5 5,5, body extent -5.02,-5.03 5.03,5.02, height 16.29
CE_Mark_5mm [mm] "Minimum text height for CE Mark"
  silkscreen extent -3.5,-2.5 3.5,2.5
